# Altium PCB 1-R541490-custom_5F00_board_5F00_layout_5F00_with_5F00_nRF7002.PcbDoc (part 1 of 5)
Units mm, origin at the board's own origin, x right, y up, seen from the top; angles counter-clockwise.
Board outline 180 x 80 mm, 6 copper layers (Top Layer, GND 1, Signal 1, POWER, GND 2, Bottom Layer), stack 1.609 mm thick; 321 components, 275 nets, 828 pads, 1164 vias.
Unrouted connection lines stored in the file: 746.
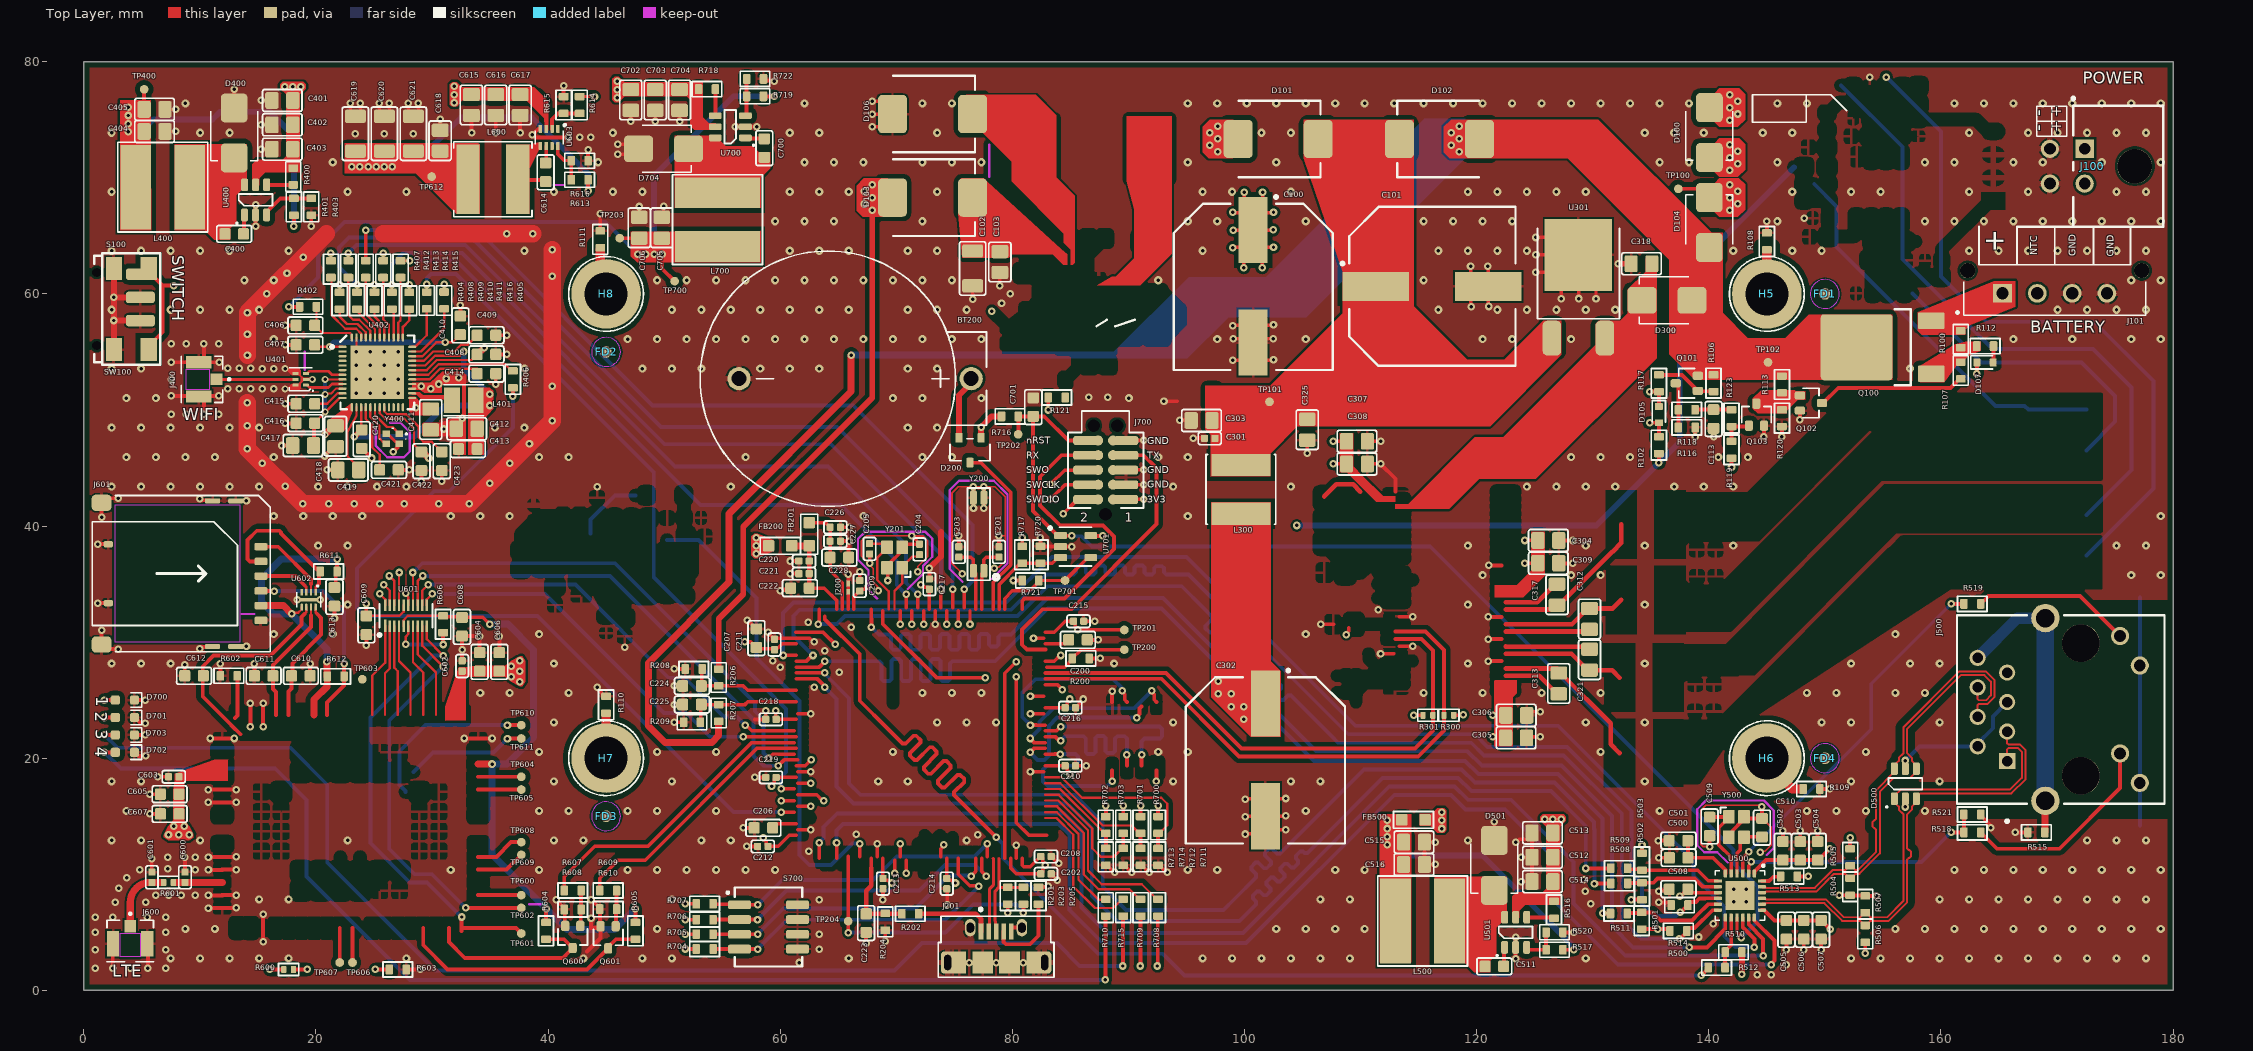
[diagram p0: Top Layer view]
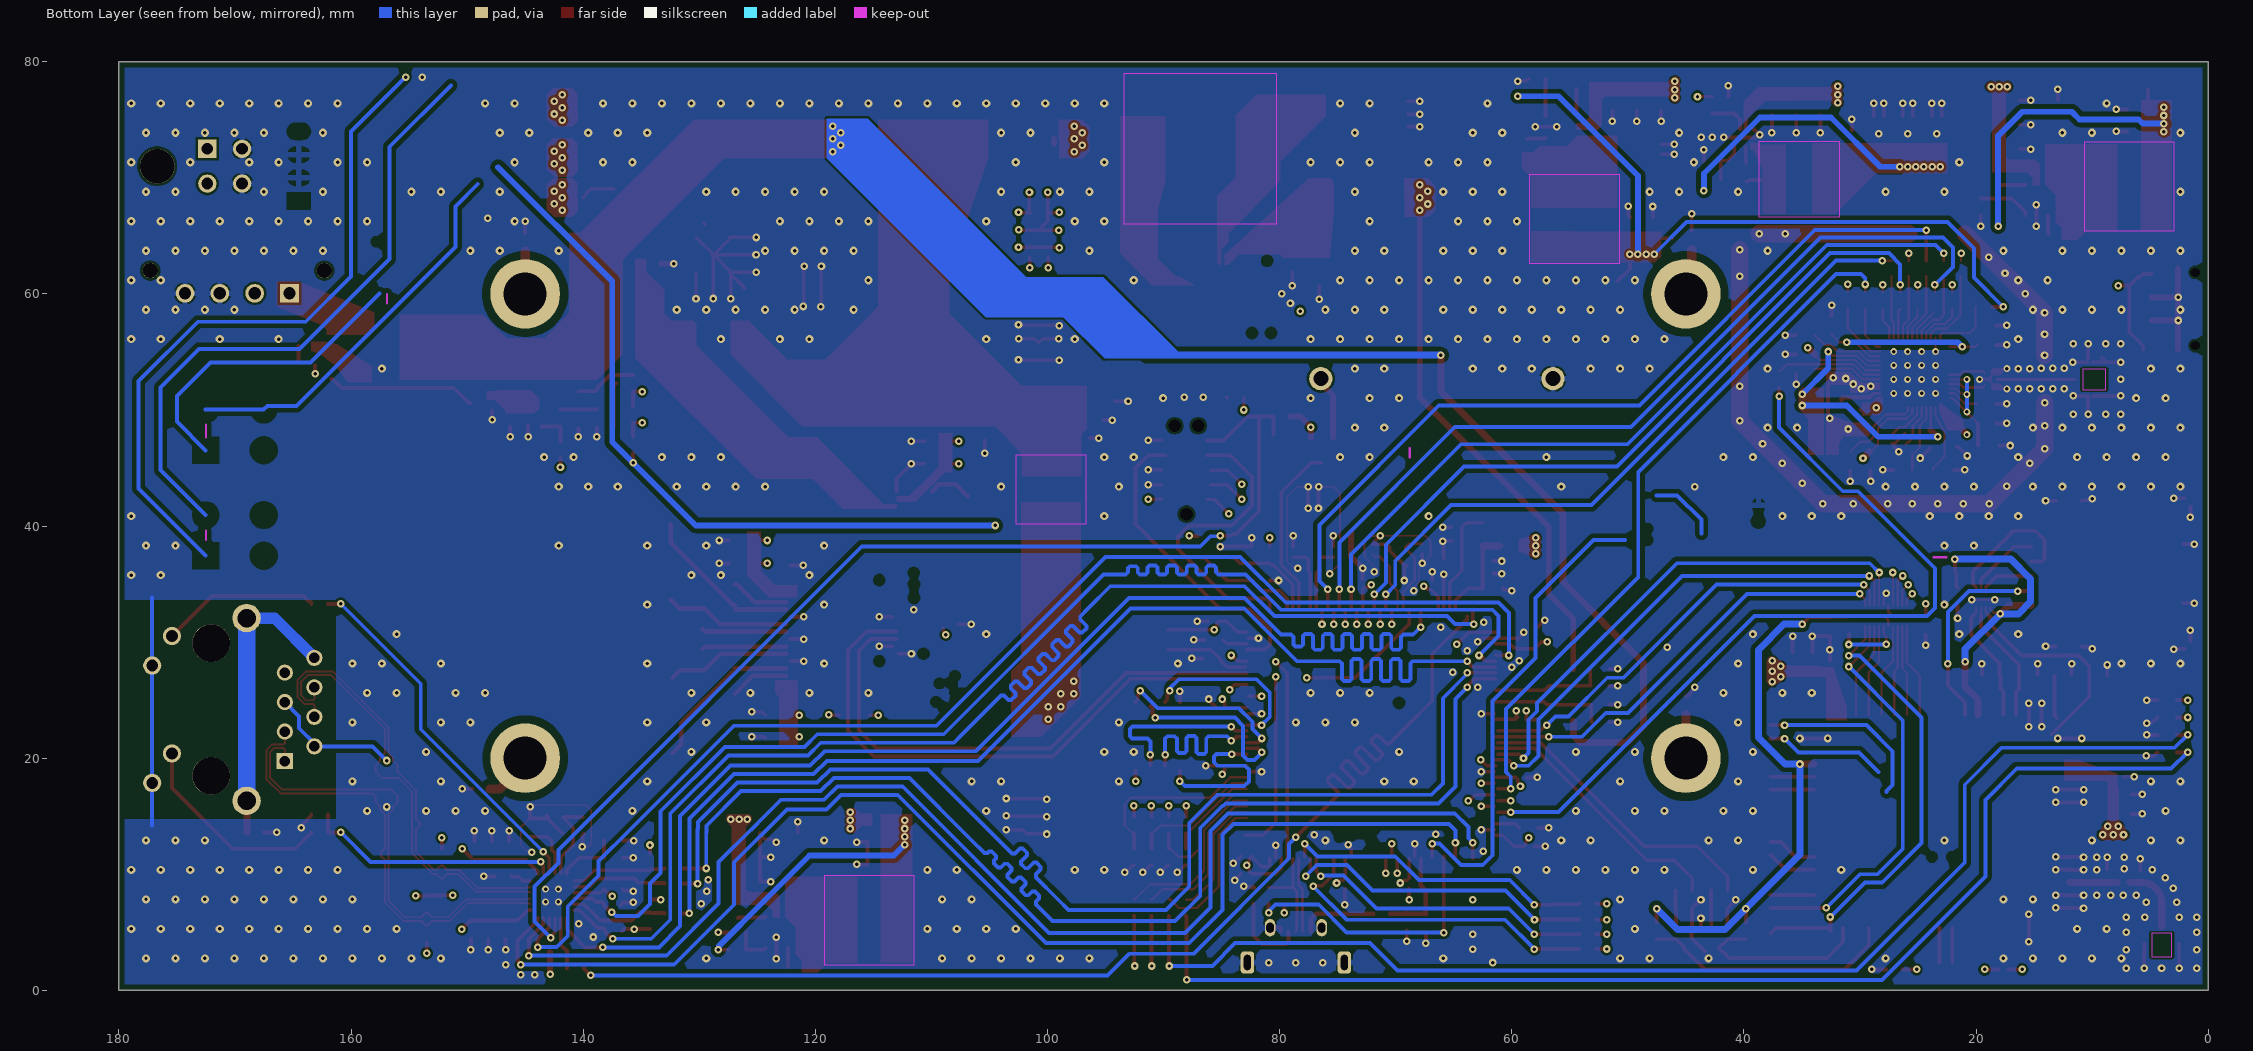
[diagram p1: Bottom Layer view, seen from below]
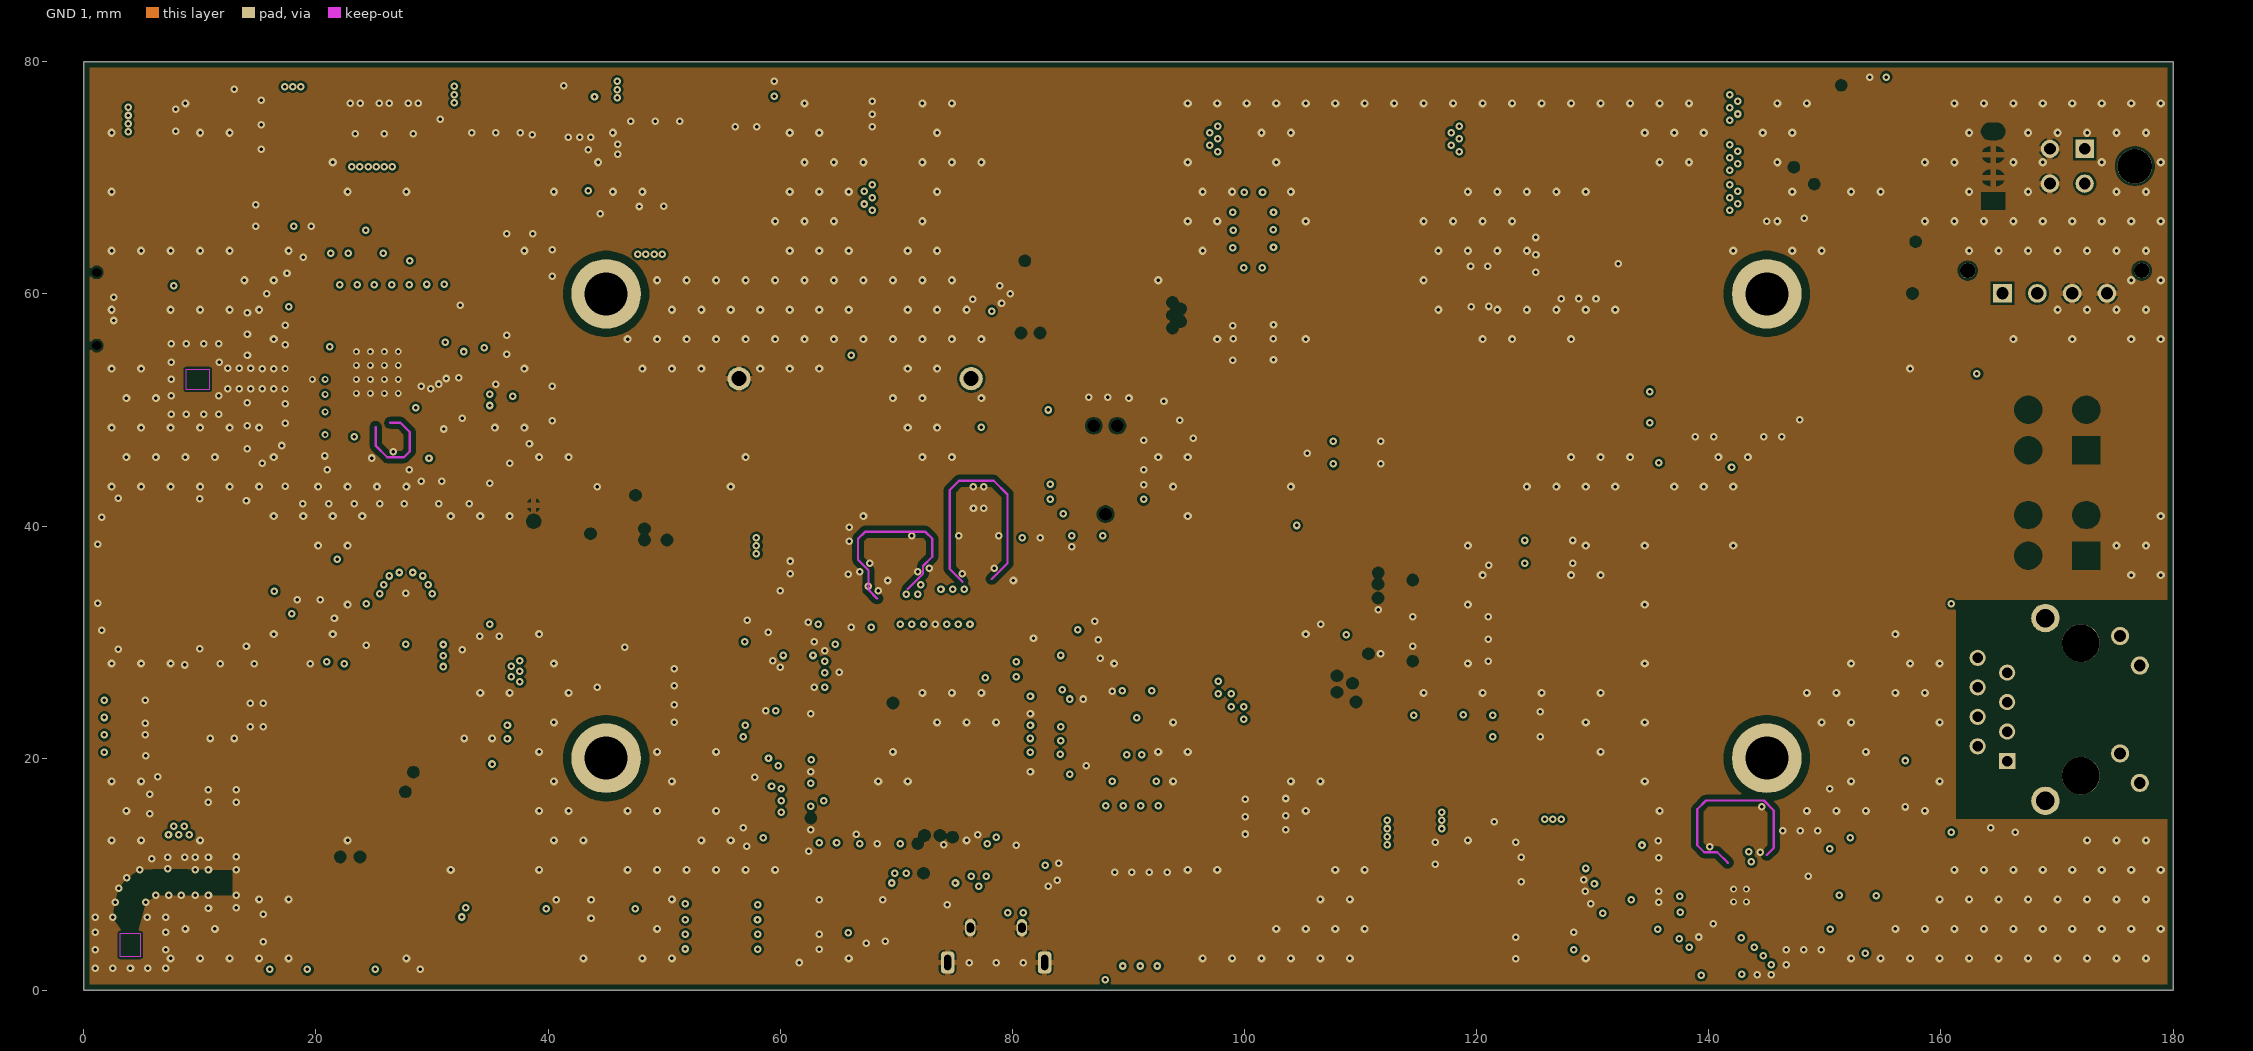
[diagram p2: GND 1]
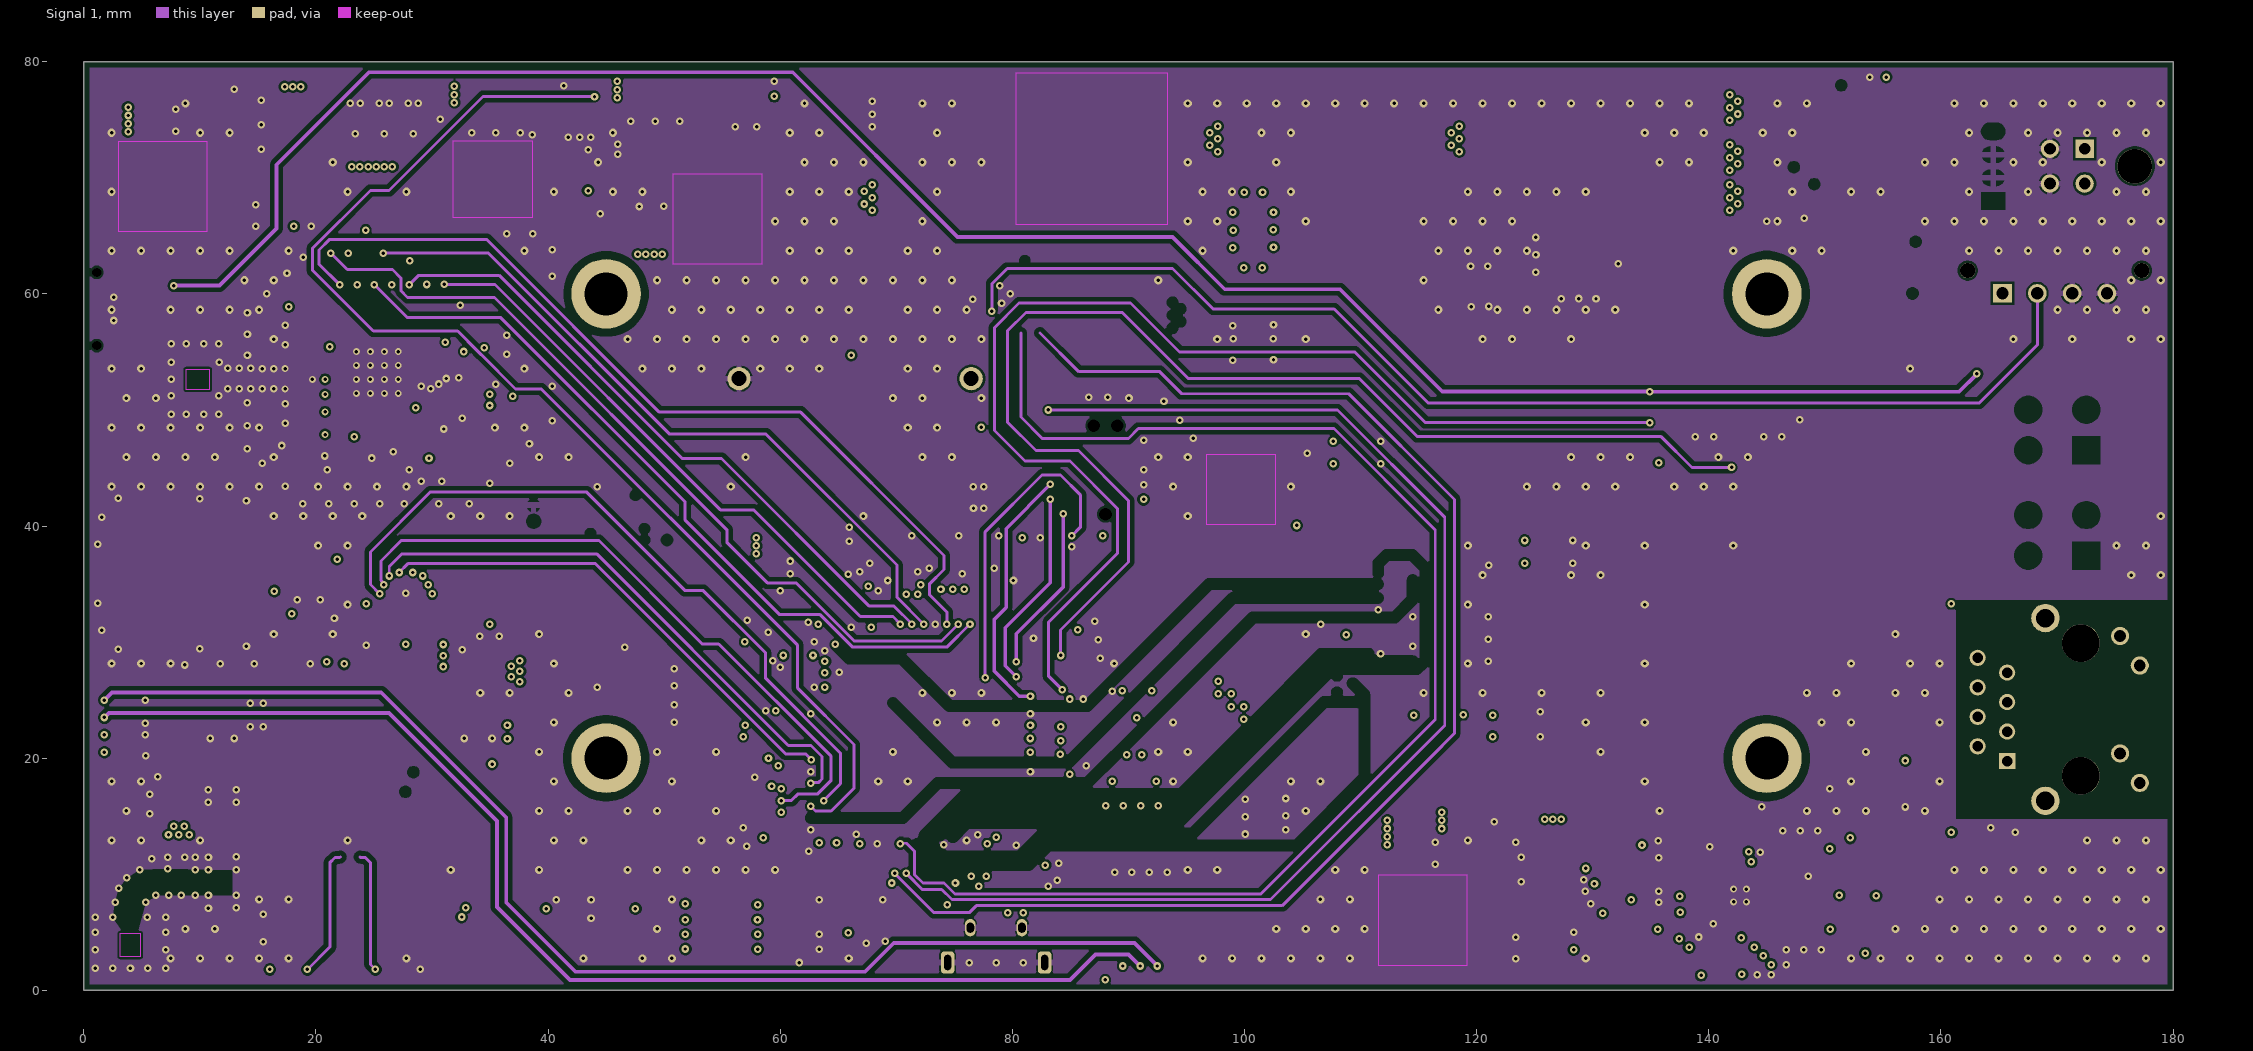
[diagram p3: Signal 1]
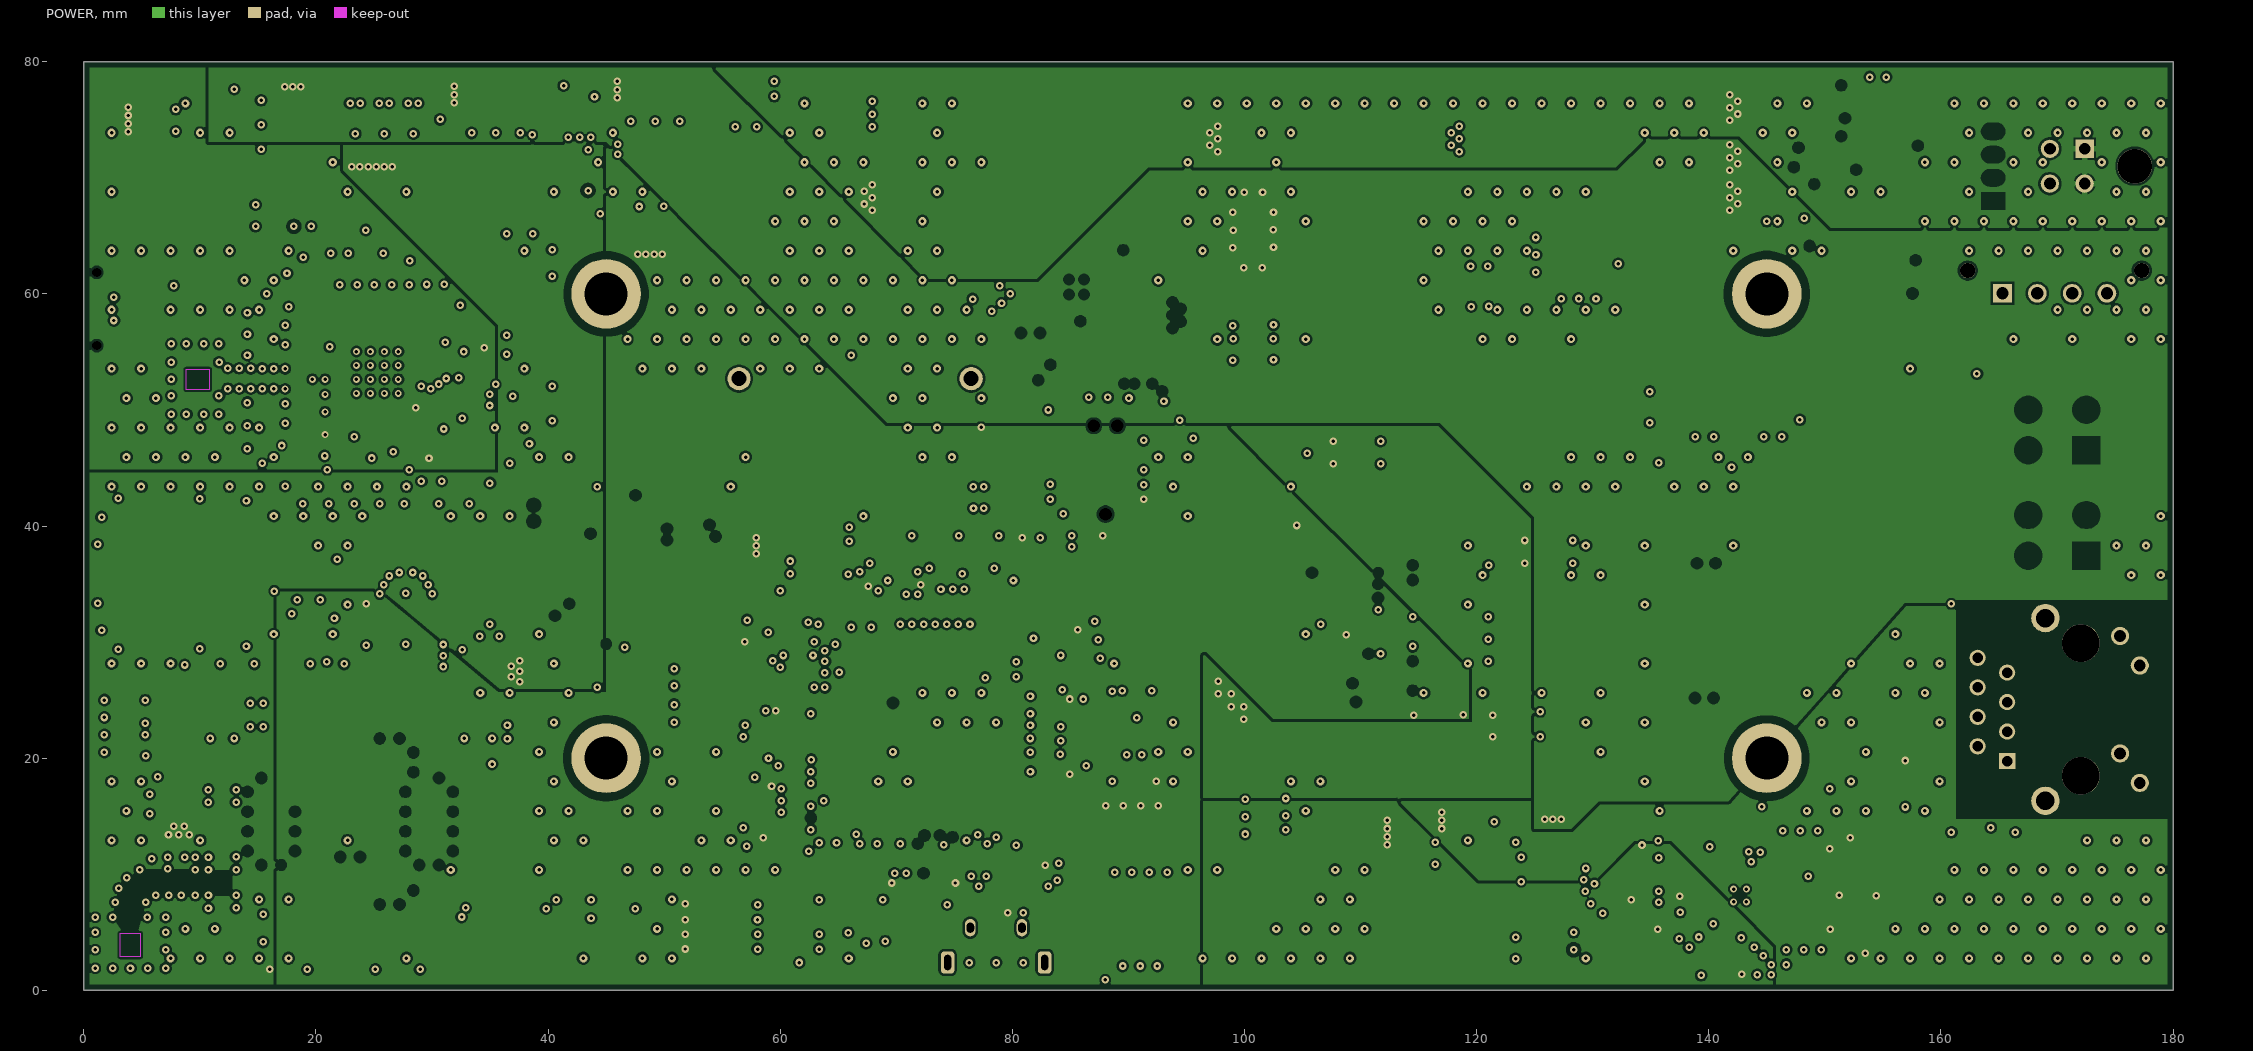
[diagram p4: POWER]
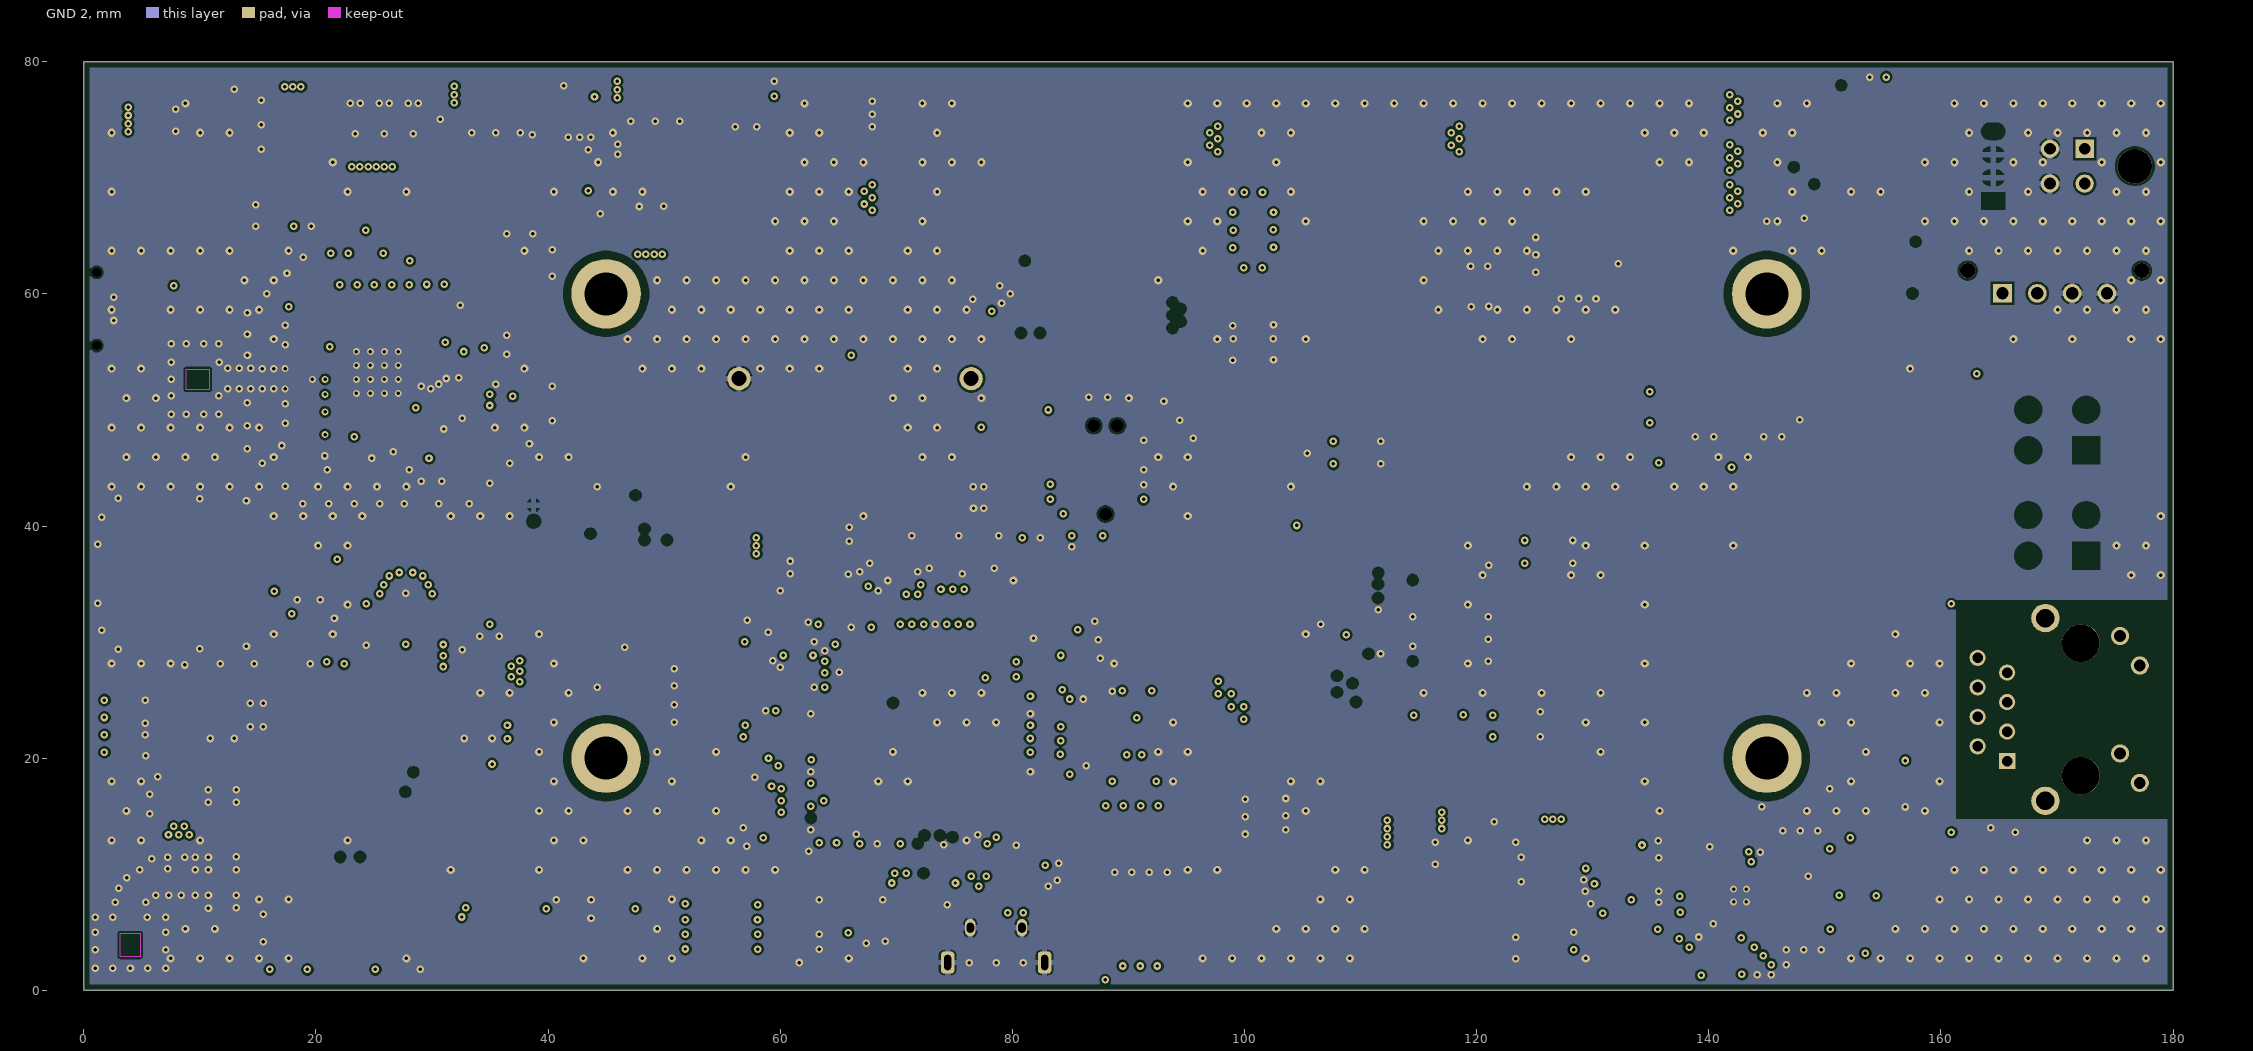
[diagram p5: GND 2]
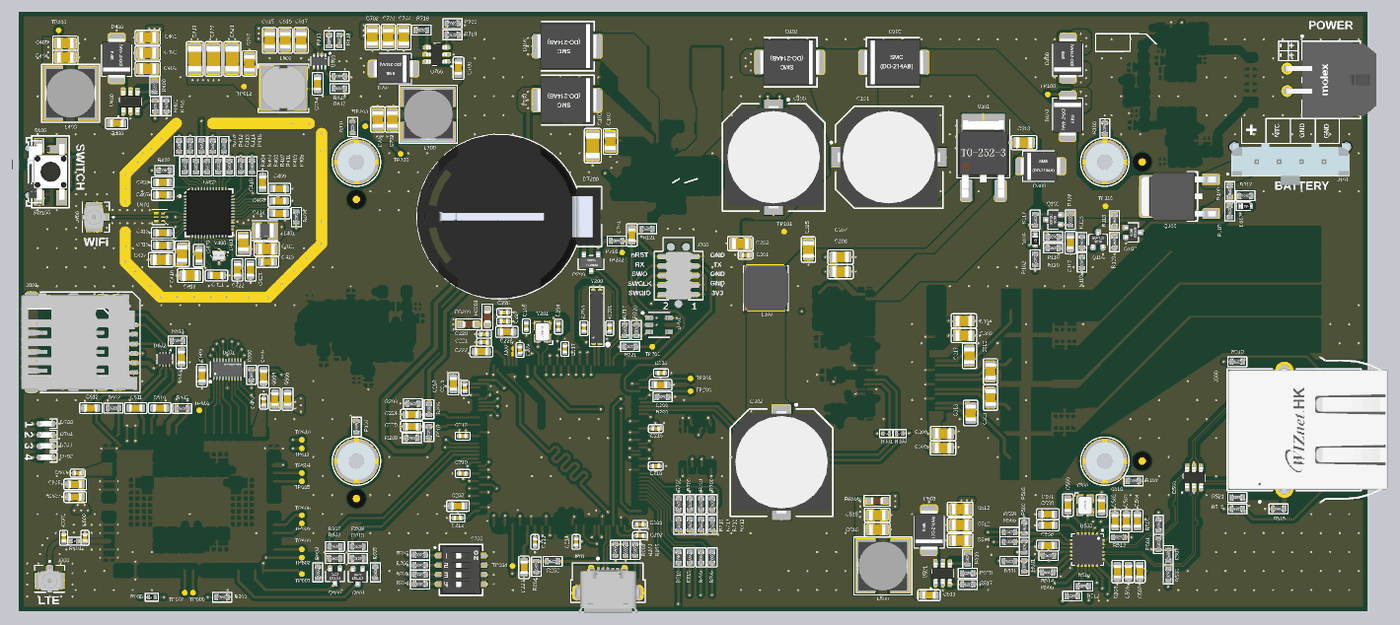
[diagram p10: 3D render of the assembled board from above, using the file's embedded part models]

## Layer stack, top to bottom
Top Solder: solder mask 0.0254, Dk 4
Top Layer: signal copper 0.035
Dielectric 1: prepreg 0.203, Dk 4.4
GND 1: signal copper 0.03
Dielectric 3: core 0.25, Dk 4.6
Signal 1: signal copper 0.03
Dielectric 4: prepreg 0.203, Dk 4.4
Dielectric 2: prepreg 0.107, Dk 4.1
Dielectric 5: prepreg 0.203, Dk 4.4
POWER: signal copper 0.03
Dielectric 6: core 0.25, Dk 4.6
GND 2: signal copper 0.03
Dielectric 8: prepreg 0.203, Dk 4.4
Bottom Layer: signal copper 0.035
Bottom Solder: solder mask 0.0254, Dk 4

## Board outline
0,0 0,80 180,80 180,0

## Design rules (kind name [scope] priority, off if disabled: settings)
BoardOutlineClearance [All] p1: gap=0.5 ignorepadtopadclearanceinfootprint=FALSE
Clearance Clearance_LTE [InNetClass('ANT_LTE')] p1: gap=0.155 ignorepadtopadclearanceinfootprint=TRUE
Clearance Clearance_BLE [InNetClass('ANT_BLE')] p2: gap=0.15 ignorepadtopadclearanceinfootprint=TRUE
Clearance Clearance_QSPI [InNetClass('QSPI')] p3: gap=0.2 ignorepadtopadclearanceinfootprint=TRUE except(0.4: Arc-Fill Arc-Poly Arc-Region Track-Fill Track-Poly Track-Region)
Clearance Clearance_RMII [InNetClass('RMII')] p4: gap=0.2 ignorepadtopadclearanceinfootprint=TRUE except(0.4: Arc-Fill Arc-Poly Arc-Region Track-Fill Track-Poly Track-Region)
Clearance "Clearance_Dif To Poly" [InNetClass('USB') or InNetClass('Ethernet')] p5: gap=0.15 ignorepadtopadclearanceinfootprint=TRUE except(0.6: Track-Poly)
Clearance Clearance_H5-H8 [InNet('NetH5_1') or InNet('NetH6_1') or InNet('NetH7_1') or InNet('NetH8_1')] p6: gap=0.7 ignorepadtopadclearanceinfootprint=TRUE
Clearance Clearance_All [All] p7: gap=0.2 ignorepadtopadclearanceinfootprint=TRUE except(0.15: Arc-Arc Arc-Track Arc-SMDPad Arc-Via Arc-Fill Arc-Poly Arc-Region Track-Track Track-SMDPad Track-Via Track-Fill Track-Region SMDPad-Via SMDPad-Fill SMDPad-Region; 0.3: Poly-Poly; 0.4: Track-Poly SMDPad-Poly)
ComponentClearance [All] p1: gap=0 collisioncheckmode=3 verticalgap=0 showdistances=FALSE
DiffPairsRouting Diff_100 [InDifferentialPair('RD') or InDifferentialPair('TD')] p1: maxlimit=0.15 minlimit=0.127 mostfreqgap=0.127 toplayer_mingap=0.15 toplayer_prefgap=0.15 toplayer_minwidth=0.17 toplayer_maxwidth=0.17 toplayer_prefwidth=0.17 bottomlayer_mingap=0.15 bottomlayer_prefgap=0.15 bottomlayer_minwidth=0.17 bottomlayer_maxwidth=0.17 bottomlayer_prefwidth=0.17 impedanceprofiledriven=TRUE impedanceprofileid={3A594C90-DEC5-4F1F-8E79-E24C382BD90D} impedanceprofilevalue=100.000000 maxuncoupledlength=12.7
DiffPairsRouting Diff_90 [InDifferentialPair('USB')] p2: maxlimit=0.25 minlimit=0.127 mostfreqgap=0.127 toplayer_mingap=0.2 toplayer_maxgap=0.2 toplayer_prefgap=0.2 toplayer_minwidth=0.27 toplayer_maxwidth=0.27 toplayer_prefwidth=0.27 bottomlayer_mingap=0.2 bottomlayer_maxgap=0.2 bottomlayer_prefgap=0.2 bottomlayer_minwidth=0.27 bottomlayer_maxwidth=0.27 bottomlayer_prefwidth=0.27 impedanceprofiledriven=TRUE impedanceprofileid={268F52A2-5A94-457B-AB45-65FDFB8BE8B0} impedanceprofilevalue=90.000000 maxuncoupledlength=12.7
HoleSize [All] p1: absolutevalues=TRUE maxlimit=5 minlimit=0.3 maxpercent=80.000 minpercent=20.000
MatchedLengths xSignals_Ethernet_Group [InxSignalClass('Ethernet')] p1: tolerance=1.3 checknetsindiffpair=FALSE checkdiffpairvsdiffpair=TRUE checkxsignals=TRUE checkothers=TRUE usedelayunits=TRUE delaytolerance=330.000000
MatchedLengths xSignals_Ethernet_DP [InxSignalClass('Ethernet')] p2: tolerance=1.3 checknetsindiffpair=TRUE checkdiffpairvsdiffpair=FALSE checkxsignals=FALSE checkothers=FALSE usedelayunits=TRUE delaytolerance=1.600000
MatchedLengths xSignals_QSPI [InxSignalClass('QSPI')] p3: tolerance=1.3 checknetsindiffpair=FALSE checkdiffpairvsdiffpair=TRUE checkxsignals=TRUE checkothers=TRUE usedelayunits=TRUE delaytolerance=1.600000
MatchedLengths xSignals_RMII [InxSignalClass('RMII')] p4: tolerance=1.3 checknetsindiffpair=FALSE checkdiffpairvsdiffpair=TRUE checkxsignals=TRUE checkothers=TRUE usedelayunits=TRUE delaytolerance=1.600000
MinimumSolderMaskSliver [All] p1: minsoldermaskwidth=0.05
PasteMaskExpansion [All] p1: expansion=-0.05
PlaneClearance [All] p1: clearance=0.152
PlaneConnect [All] p1: planeconnectstyle=Direct reliefexpansion=0.508 reliefentries=4 reliefconductorwidth=0.254 reliefairgap=0.254
PolygonConnect PolygonConnect_All [All] p1: thpad.connectstyle=Relief thpad.reliefconductorwidth=0.5 thpad.reliefentries=4 thpad.polygonreliefangle="90 Angle" thpad.airgapwidth=0.15 smdpad.connectstyle=Relief smdpad.reliefconductorwidth=0.254 smdpad.reliefentries=4 smdpad.polygonreliefangle="90 Angle" smdpad.airgapwidth=0.15 via.connectstyle=Direct via.reliefconductorwidth=0.254 via.reliefentries=4 via.polygonreliefangle="90 Angle" via.airgapwidth=0.254
RoutingVias [All] p1: holewidth=0.3 width=0.6 viastyle="Through Hole" minholewidth=0.3 minwidth=0.3 maxholewidth=0.6 maxwidth=1
SilkToSilkClearance [All] p1: silktosilkclearance=0.2
SilkToSolderMaskClearance [IsPad] p1: minsilkscreentomaskgap=0.025 clearancetoexposedcopper=TRUE
SolderMaskExpansion [All] p1: expansion=0.05 istentingtop=FALSE
SupplyNets "Schematic Supply Nets_9" [InNet('VDD_MCU')] p1: voltage=0.000
SupplyNets "Schematic Supply Nets_7" [InNet('VBAT_nRF')] p2: voltage=0.000
SupplyNets "Schematic Supply Nets_18" [InNet('+VCC_Ampl')] p3: voltage=0.000
SupplyNets "Schematic Supply Nets_17" [InNet('VDDA')] p4: voltage=0.000
SupplyNets "Schematic Supply Nets_15" [InNet('VREF+')] p5: voltage=0.000
SupplyNets "Schematic Supply Nets_13" [InNet('PVDD')] p6: voltage=0.000
SupplyNets "Schematic Supply Nets_12" [InNet('VIN')] p7: voltage=0.000
SupplyNets "Schematic Supply Nets_11" [InNet('GND')] p8: voltage=0.000
SupplyNets "Schematic Supply Nets_4" [InNet('+1.8V_modem')] p9: voltage=0.000
SupplyNets "Schematic Supply Nets" [InNet('+VCC_modem')] p10: voltage=0.000
SupplyNets "Schematic Supply Nets_8" [InNet('VCC_Ethr')] p11: voltage=0.000
SupplyNets "Schematic Supply Nets_6" [InNet('VCC')] p12: voltage=0.000
SupplyNets "Schematic Supply Nets_3" [InNet('VBAT')] p13: voltage=0.000
SupplyNets "Schematic Supply Nets_2" [InNet('PWRIOVDD')] p14: voltage=0.000
SupplyNets "Schematic Supply Nets_1" [InNet('VDD_BUCK')] p15: voltage=0.000
Width RF_ANT_BLE [InNetClass('ANT_BLE')] p1: maxlimit=0.25 minlimit=0.152 preferedwidth=0.234 toplayer_minwidth=0.25 toplayer_prefwidth=0.25 impedanceprofiledriven=TRUE impedanceprofileid={3CCB0671-2807-4B09-B0E4-ECFB67FC63CC} impedanceprofilevalue=50.000000 minimp=50.000000 maximp=50.000000 favimp=50.000000
Width RMII [InNetClass('RMII')] p2: maxlimit=0.478 minlimit=0.152 preferedwidth=0.256 toplayer_minwidth=0.3 toplayer_maxwidth=0.335 toplayer_prefwidth=0.335 midlayer1_minwidth=0.256 midlayer1_maxwidth=0.256 midlayer2_minwidth=0.256 midlayer2_maxwidth=0.256 bottomlayer_minwidth=0.3 bottomlayer_maxwidth=0.335 bottomlayer_prefwidth=0.335 impedanceprofiledriven=TRUE impedanceprofileid={89E4D563-145F-4F12-8B66-BC4C088131D8} impedanceprofilevalue=50.000000 minimp=50.000000 maximp=50.000000 favimp=50.000000
Width RF_ANT_LTE_1 [InNetClass('ANT_LTE')] p3: maxlimit=0.62 minlimit=0.152 preferedwidth=0.234 toplayer_minwidth=0.62 toplayer_prefwidth=0.62 impedanceprofiledriven=TRUE impedanceprofileid={F6C68C6A-9B4C-40B1-A6B1-C1A082B88F94} impedanceprofilevalue=50.000000 minimp=50.000000 maximp=50.000000 favimp=50.000000
Width "Tracks Z=50 Ohm" [InNetClass('50 Ohm')] p4: maxlimit=0.344 minlimit=0.256 preferedwidth=0.344 toplayer_minwidth=0.335 toplayer_maxwidth=0.335 toplayer_prefwidth=0.335 midlayer1_maxwidth=0.256 midlayer1_prefwidth=0.256 midlayer2_maxwidth=0.256 midlayer2_prefwidth=0.256 bottomlayer_minwidth=0.335 bottomlayer_maxwidth=0.335 bottomlayer_prefwidth=0.335 impedanceprofiledriven=TRUE impedanceprofileid={89E4D563-145F-4F12-8B66-BC4C088131D8} impedanceprofilevalue=50.000000 minimp=50.000000 maximp=50.000000 favimp=50.000000
Width ALL_TRACKS [All] p5: maxlimit=5 minlimit=0.14 preferedwidth=0.152 midlayer3_prefwidth=0.254 midlayer4_prefwidth=0.254 minimp=50.000000 maximp=50.000000 favimp=50.000000
21 further rules are at their usual default settings.

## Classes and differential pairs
net class QSPI: CLK CS HOLD MISO MOSI WP
net class SIM: SIM_C_CLK SIM_C_DATA SIM_C_RST SIM_CLK sim_connector.SIM_DATA sim_connector.SIM_RST
differential pair class DIFF90: USB
differential pair class DIFF100: RD TD
net class USB: USB_N USB_P
net class RMII: NetR501_1 NetR502_1 NetR503_1 RMII_CRS_DV RMII_MDC RMII_MDIO RMII_REF_CLK RMII_RX_ER RMII_RXD0 RMII_RXD1 RMII_TX_EN RMII_TXD0 RMII_TXD1
net class Ethernet: RD_N RD_P TD_N TD_P
net class ANT_LTE: ANT_LTE_1 ANT_LTE_2
net class ANT_BLE: NetJ400_1 TXRF0 TXRF1
net class "50 Ohm": NetR501_1 NetR502_1 NetR503_1 RMII_CRS_DV RMII_MDC RMII_MDIO RMII_REF_CLK RMII_RX_ER RMII_RXD0 RMII_RXD1 RMII_TX_EN RMII_TXD0 RMII_TXD1
component class Power: C100 C101 C102 C113 D100 D101 D102 D103 D104 D105 D106 D107 J100 J101 Q100 Q101 Q102 Q103 R100 R102 R106 R107 R112 R113 R116 R117 R118 R119 R120 R121 R123 S100 SW100 TP100 TP101 TP102
component class MCU: BT200 C200 C201 C202 C203 C204 C205 C206 C207 C208 C209 C210 C211 C212 C213 C214 C215 C216 C217 C218 C219 C220 C221 C222 C223 C224 C225 C226 C227 C228 D200 FB200 FB201 J200 J201 R200 R201 R202 R203 R204 R205 R206 R207 R208 R209 TP200 TP201 TP202 TP203 TP204 Y200 Y201
component class Debug: C700 C701 C702 C703 C704 C705 C706 D700 D701 D702 D703 D704 J700 L700 R700 R701 R702 R703 R704 R705 R706 R707 R708 R709 R710 R711 R712 R713 R714 R715 R716 R717 R718 R719 R720 R721 R722 S700 TP700 TP701 U700 U701
component class "LTE Modem": C600 C601 C602 C603 C604 C605 C606 C607 C608 C609 C610 C611 C612 C613 C614 C615 C616 C617 C618 C619 C620 C621 J600 J601 L600 Q600 Q601 R600 R601 R602 R603 R604 R605 R606 R607 R608 R609 R610 R611 R612 R613 R614 R615 R616 TP600 TP601 TP602 TP603 TP604 TP605 TP606 TP607 TP608 TP609 TP610 TP611 TP612 U601 U602 U603
component class Ethernet: C500 C501 C502 C503 C504 C505 C506 C507 C508 C509 C510 C511 C512 C513 C514 C515 C516 D500 D501 FB500 J500 L500 R500 R501 R502 R503 R504 R505 R506 R507 R508 R509 R510 R511 R512 R513 R514 R515 R516 R517 R518 R519 R520 R521 U500 U501 Y500
component class Amplifier: C301 C302 C303 C304 C305 C306 C307 C308 C309 C312 C313 C317 C318 C321 C325 D300 L300 R300 R301 U301
component class WiFi: C400 C401 C402 C403 C404 C405 C406 C407 C408 C409 C410 C411 C412 C413 C414 C415 C416 C417 C418 C419 C420 C421 C422 C423 D400 J400 L400 L401 R400 R401 R402 R403 R404 R405 R406 R407 R408 R409 R410 R411 R412 R413 R414 R415 R416 TP400 U400 U401 U402 Y400
component class MSheet: FD1 FD2 FD3 FD4 GS1 H5 H6 H7 H8 R108 R109 R110 R111
differential pair USB: +USB_P -USB_N
differential pair TD: +TD_P -TD_N
differential pair RD: +RD_P -RD_N

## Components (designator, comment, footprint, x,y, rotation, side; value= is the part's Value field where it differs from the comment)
BT200 "BH-25F-1" BH-25F-1 64.45,52.7 r0 top
C100 "EMVA500ARA471MKG5S" EMVA500ARA471MKG5S 100.75,60.65 r270 top value=470µF
C101 "EMVA500ARA471MKG5S" EMVA500ARA471MKG5S 116.15,60.65 r0 top value=470µF
C102 "GRM31CR71H475KA12L" B_Cap_1206_KEM 76.575,62.196 r90 top value=4.7µF
C103 "CC0805KRX7R9BB104" B_Cap_0805_KEM 78.925,62.746 r90 top value=100nF
C113 "GRM188R61C106KAALJ" B_Cap_0603_KEM 140.407,49.226 r90 top value=10µF
C200 "CL10B225KP8NNNC" B_Cap_0603_KEM 85.65,30.2 r180 top value=2.2µF
C201 "GRM1555C1H3R3WA01D" B_Cap_0402_KEM 78.842,37.775 r270 top value=3.3pF
C202 "EMK105BJ105KV-F" B_Cap_0402_KEM 82.899,10.04 r0 top value=1µF
C203 "GRM1555C1H3R3WA01D" B_Cap_0402_KEM 75.387,37.775 r90 top value=3.3pF
C204 "CC0402BRNPO9BN2R7" B_Cap_0402_KEM 72,37.99 r90 top value=2.7pF
C205 "CC0402BRNPO9BN2R7" B_Cap_0402_KEM 67.7,38.04 r270 top value=2.7pF
C206 "CL10B225KP8NNNC" B_Cap_0603_KEM 58.55,14 r0 top value=2.2µF
C207 "GCM188R71H104KA57D" B_Cap_0603_KEM 57.95,30.35 r270 top value=100nF
C208 "CL05A475MO5NUNC" B_Cap_0402_KEM 82.899,11.54 r180 top value=4.7µF
C209 "GRM155R71H104ME14D" B_Cap_0402_KEM 66.85,34.861 r270 top value=100nF
C210 "GRM155R71H104ME14D" B_Cap_0402_KEM 85,19.35 r180 top value=100nF
C211 "GRM155R71H104ME14D" B_Cap_0402_KEM 59.5,29.8 r270 top value=100nF
C212 "GRM155R71H104ME14D" B_Cap_0402_KEM 58.5,12.4 r0 top value=100nF
C213 "GRM155R71H104ME14D" B_Cap_0402_KEM 68.85,9.2 r90 top value=100nF
C214 "GRM155R71H104ME14D" B_Cap_0402_KEM 74.35,9.2 r90 top value=100nF
C215 "GRM155R71H104ME14D" B_Cap_0402_KEM 85.7,31.8 r180 top value=100nF
C216 "GRM155R71H104ME14D" B_Cap_0402_KEM 85,24.35 r180 top value=100nF
C217 "GRM155R71H104ME14D" B_Cap_0402_KEM 72.85,35 r270 top value=100nF
C218 "GRM155R71H104ME14D" B_Cap_0402_KEM 59.2,23.35 r0 top value=100nF
C219 "GRM155R71H104ME14D" B_Cap_0402_KEM 59.2,18.35 r0 top value=100nF
C220 "EMK105BJ105KV-F" B_Cap_0402_KEM 62.05,36.989 r0 top value=1µF
C221 "GRM155R71H104ME14D" B_Cap_0402_KEM 62.05,35.899 r0 top value=100nF
C222 "CC0603MRX7R9BB103" B_Cap_0603_KEM 61.7,34.654 r0 top value=10nF
C223 "GCM188R71H104KA57D" B_Cap_0603_KEM 67.4,5.8 r90 top value=100nF
C224 "GCM188R71H104KA57D" B_Cap_0603_KEM 52.4,26.225 r0 top value=100nF
C225 "GCM188R71H104KA57D" B_Cap_0603_KEM 52.4,24.625 r0 top value=100nF
C226 "EMK105BJ105KV-F" B_Cap_0402_KEM 64.75,39.9 r180 top value=1µF
C227 "GRM155R71H104ME14D" B_Cap_0402_KEM 64.75,38.7 r180 top value=100nF
C228 "CC0603MRX7R9BB103" B_Cap_0603_KEM 65.1,37.29 r180 top value=10nF
C301 "CC0402JRX7R9BB222" B_Cap_0402_KEM 97,47.55 r0 top value=2.2nF
C302 "EMVA500ARA471MKG5S" EMVA500ARA471MKG5S 101.8,19.85 r270 top value=470µF
C303 "CC0805KRX7R9BB104" B_Cap_0805_KEM 96.3,49.1 r0 top value=100nF
C304 "CL21B105KBFNNNG" B_Cap_0805_KEM 126.175,38.757 r180 top value=1µF
C305 "CL21B105KBFNNNG" B_Cap_0805_KEM 123.391,21.757 r180 top value=1µF
C306 "CC0805KRX7R9BB104" B_Cap_0805_KEM 123.407,23.69 r180 top value=100nF
C307 "CL21B105KBFNNNG" B_Cap_0805_KEM 109.69,47.3 r180 top value=1µF
C308 "CC0805KRX7R9BB104" B_Cap_0805_KEM 109.69,45.35 r180 top value=100nF
C309 "CC0805KRX7R9BB104" B_Cap_0805_KEM 126.175,36.803 r180 top value=100nF
C312 "CL21B105KBFNNNG" B_Cap_0805_KEM 129.725,28.49 r90 top value=1µF
C313 "CL21B105KBFNNNG" B_Cap_0805_KEM 127.075,26.44 r270 top value=1µF
C317 "CL21B105KBFNNNG" B_Cap_0805_KEM 126.925,34.09 r90 top value=1µF
C318 "CC0805KRX7R9BB104" B_Cap_0805_KEM 134.2,62.6 r0 top value=100nF
C321 "CL21B105KBFNNNG" B_Cap_0805_KEM 129.725,32.002 r270 top value=1µF
C325 "CC0805KRX7R9BB104" B_Cap_0805_KEM 105.4,48.3 r90 top value=100nF
C400 "GCM188R71H104KA57D" B_Cap_0603_KEM 12.96,65.17 r0 top value=100nF
C401 "CL21B105KBFNNNG" B_Cap_0805_KEM 17.108,76.67 r180 top value=1µF
C402 "CL21B105KBFNNNG" B_Cap_0805_KEM 17.108,74.57 r180 top value=1µF
C403 "CC0805KRX7R9BB104" B_Cap_0805_KEM 17.108,72.47 r0 top value=100nF
C404 "GRM21BR71C475KE51L" B_Cap_0805_KEM 6.1,75.9 r180 top value=4.7µF
C405 "GRM21BR71C475KE51L" B_Cap_0805_KEM 6.1,74 r180 top value=4.7µF
C406 "CL10B225KP8NNNC" B_Cap_0603_KEM 19.094,57.287 r0 top value=2.2µF
C407 "GCM188R71H104KA57D" B_Cap_0603_KEM 19.094,55.612 r0 top value=100nF
C408 "CL10B225KP8NNNC" B_Cap_0603_KEM 34.694,54.787 r180 top value=2.2µF
C409 "CL10B105KA8NNNC" B_Cap_0603_KEM 34.694,56.437 r180 top value=1µF
C410 "CL10B225KP8NNNC" B_Cap_0603_KEM 32.444,57.287 r270 top value=2.2µF
C411 "GRM21BR71C475KE51L" B_Cap_0805_KEM 29.894,49.187 r90 top value=4.7µF
C412 "GRM21BR71C475KE51L" B_Cap_0805_KEM 32.994,48.387 r0 top value=4.7µF
C413 "CL10A474KB8NNNC" B_Cap_0603_KEM 33.094,46.637 r0 top value=470nF
C414 "CC0603MRX7R9BB103" B_Cap_0603_KEM 34.694,53.137 r180 top value=10nF
C415 "CL10A474KB8NNNC" B_Cap_0603_KEM 19.094,50.537 r0 top value=470nF
C416 "GCM188R71H104KA57D" B_Cap_0603_KEM 19.094,48.866 r0 top value=100nF
C417 "GRM21BR71C475KE51L" B_Cap_0805_KEM 18.894,46.937 r0 top value=4.7µF
C418 "GRM21BR71C475KE51L" B_Cap_0805_KEM 21.694,47.737 r90 top value=4.7µF
C419 "CC0805KRX7R9BB223" B_Cap_0805_KEM 22.794,44.837 r0 top value=22nF
C420 "C0603C224K4RAC7411" B_Cap_0603_KEM 23.944,47.487 r270 top value=220nF
C421 "CL10B225KP8NNNC" B_Cap_0603_KEM 26.294,44.837 r180 top value=2.2µF
C422 "CL10B105KA8NNNC" B_Cap_0603_KEM 29.094,45.587 r90 top value=1µF
C423 "CL10B105KA8NNNC" B_Cap_0603_KEM 30.844,45.587 r90 top value=1µF
C500 "VJ0603Y471KLAAJ32" B_Cap_0603_KEM 137.403,11.422 r0 top value=470pF
C501 "CL10B105KA8NNNC" B_Cap_0603_KEM 137.388,12.898 r0 top value=1µF
C502 "GCM188R71H104KA57D" B_Cap_0603_KEM 146.378,12.022 r270 top value=100nF
C503 "GCM188R71H104KA57D" B_Cap_0603_KEM 147.878,12.022 r270 top value=100nF
C504 "GCM188R71H104KA57D" B_Cap_0603_KEM 149.378,12.022 r270 top value=100nF
C505 "GCM188R71H104KA57D" B_Cap_0603_KEM 146.678,5.222 r90 top value=100nF
C506 "GCM188R71H104KA57D" B_Cap_0603_KEM 148.178,5.222 r90 top value=100nF
C507 "GCM188R71H104KA57D" B_Cap_0603_KEM 149.678,5.222 r90 top value=100nF
C508 "GCM188R71H104KA57D" B_Cap_0603_KEM 137.388,8.723 r0 top value=100nF
C509 "06035A220JAT2A" B_Cap_0603_KEM 140.066,14.121 r90 top value=22pF
C510 "06035A220JAT2A" B_Cap_0603_KEM 144.578,14.022 r270 top value=22pF
C511 "GCM188R71H104KA57D" B_Cap_0603_KEM 121.519,2.069 r0 top value=100nF
C512 "CL21B105KBFNNNG" B_Cap_0805_KEM 125.667,11.469 r180 top value=1µF
C513 "CL21B105KBFNNNG" B_Cap_0805_KEM 125.667,13.569 r180 top value=1µF
C514 "CC0805KRX7R9BB104" B_Cap_0805_KEM 125.667,9.369 r0 top value=100nF
C515 "GRM21BR71C475KE51L" B_Cap_0805_KEM 114.6,12.772 r180 top value=4.7µF
C516 "GRM21BR71C475KE51L" B_Cap_0805_KEM 114.6,10.847 r180 top value=4.7µF
C600 "Cap TBD, , 0402," B_Cap_0402_KEM 8.72,9.75 r270 top
C601 "Cap TBD, , 0402," B_Cap_0402_KEM 5.87,9.74 r270 top
C602 "C0402C390J5GACTU" B_Cap_0402_KEM 32.6,27.944 r90 top value=39pF
C603 "C0402C390J5GACTU" B_Cap_0402_KEM 7.75,18.4 r0 top value=39pF
C604 "GCM188R71H104KA57D" B_Cap_0603_KEM 34.1,28.3 r90 top value=100nF
C605 "GCM188R71H104KA57D" B_Cap_0603_KEM 7.4,16.9 r0 top value=100nF
C606 "CL10A226MO7JZNC" B_Cap_0603_KEM 35.8,28.3 r90 top value=22µF
C607 "CL10A226MO7JZNC" B_Cap_0603_KEM 7.4,15.2 r0 top value=22µF
C608 "GCM188R71H104KA57D" B_Cap_0603_KEM 32.586,31.32 r270 top value=100nF
C609 "GCM188R71H104KA57D" B_Cap_0603_KEM 24.35,31.45 r270 top value=100nF
C610 "06035A220JAT2A" B_Cap_0603_KEM 18.7,27.1 r180 top value=22pF
C611 "06035A220JAT2A" B_Cap_0603_KEM 15.5,27.1 r0 top value=22pF
C612 "06035A220JAT2A" B_Cap_0603_KEM 9.5,27.1 r0 top value=22pF
C613 "CL10B105KA8NNNC" B_Cap_0603_KEM 21.6,33.9 r90 top value=1µF
C614 "GCM188R71H104KA57D" B_Cap_0603_KEM 39.794,70.476 r90 top value=100nF
C615 "CL21B105KBFNNNG" B_Cap_0805_KEM 33.394,76.276 r270 top value=1µF
C616 "CL21B105KBFNNNG" B_Cap_0805_KEM 35.494,76.276 r270 top value=1µF
C617 "CC0805KRX7R9BB104" B_Cap_0805_KEM 37.594,76.276 r90 top value=100nF
C618 "CC0805KRX7R9BB104" B_Cap_0805_KEM 30.7,73.2 r270 top value=100nF
C619 "EMK316BB7226ML-T" B_Cap_1206_KEM 23.4,73.8 r270 top value=22µF
C620 "EMK316BB7226ML-T" B_Cap_1206_KEM 25.9,73.8 r270 top value=22µF
C621 "EMK316BB7226ML-T" B_Cap_1206_KEM 28.4,73.8 r270 top value=22µF
C700 "GCM188R71H104KA57D" B_Cap_0603_KEM 58.63,72.56 r90 top value=100nF
C701 "CC0603MRX7R9BB103" B_Cap_0603_KEM 81.8,50.25 r270 top value=10nF
C702 "CL21B105KBFNNNG" B_Cap_0805_KEM 47.131,76.708 r270 top value=1µF
C703 "CL21B105KBFNNNG" B_Cap_0805_KEM 49.23,76.708 r270 top value=1µF
C704 "CC0805KRX7R9BB104" B_Cap_0805_KEM 51.33,76.708 r90 top value=100nF
C705 "GRM21BR71C475KE51L" B_Cap_0805_KEM 49.8,65.7 r270 top value=4.7µF
C706 "GRM21BR71C475KE51L" B_Cap_0805_KEM 47.85,65.7 r270 top value=4.7µF
D100 "SS210" "DO-214AA, SMB" 140.05,73.9 r90 top
D101 "SK54L-TP" "DO-214AB, SMC" 102.9,73.35 r180 top
D102 "SK54L-TP" "DO-214AB, SMC" 116.8,73.35 r0 top
D103 "SK54L-TP" "DO-214AB, SMC" 73.125,68.296 r180 top
D104 "SS210" "DO-214AA, SMB" 140.05,66.15 r270 top
D105 "1N4148WT" "SC-79, SOD-523" 135.7,49.6 r270 top
D106 "SK54L-TP" "DO-214AB, SMC" 73.125,75.496 r180 top
D107 "1N4148WT" "SC-79, SOD-523" 163.8,54.1 r0 top
D200 "BAT54C-7-F" "TO-236-3, SC-59, SOT-23-3" 76.35,46.536 r270 top
D300 "SS210" "DO-214AA, SMB" 136.4,59.45 r0 top
D400 "SS210" "DO-214AA, SMB" 12.96,73.87 r90 top
D500 "USBLC6-4SC6" SOT-23-6 156.931,17.8 r90 top
D501 "SS210" "DO-214AA, SMB" 121.519,10.769 r90 top
D700 "150060SS55040" LED_0603 3.541,25.008 r180 top
D701 "150060VS55040" LED_0603 3.541,23.508 r180 top
D702 "150060SS55040" LED_0603 3.541,20.507 r180 top
D703 "150060VS55040" LED_0603 3.541,22.006 r180 top
D704 "SS210" "DO-214AA, SMB" 49.95,72.5 r180 top
FB200 "FBMH1608HM601-T" FBMH1608HM601-T-Footprint-1 60,38.3 r180 top
FB201 "FBMH1608HM601-T" FBMH1608HM601-T-Footprint-1 62.5,39.3 r90 top
FB500 "FBMH1608HM601-T" FBMH1608HM601-T-Footprint-1 114.555,14.691 r180 top
FD1 "Fiducial" Fidutial+ 150,60 r0 top
FD2 "Fiducial" Fidutial+ 45,55 r0 top
FD3 "Fiducial" Fidutial+ 45,15 r0 top
FD4 "Fiducial" Fidutial+ 150,20 r0 top
GS1 "PCB FILE NAME" "PCB FILE NAME" 202.5,78.2 r0 top
H5 "9774090151R" 9774090151R 145,60 r0 top
H6 "9774090151R" 9774090151R 145,20 r0 top
H7 "9774090151R" 9774090151R 45,20 r0 top
H8 "9774090151R" 9774090151R 45,60 r0 top
J100 "43045-0400" 43045-0400-Footprint-1 176.345,71 r90 top
J101 "43650-0415" 0436500415 169.8,60.05 r180 top
J200 "NetTie" NetTie_2way_LP 65.85,34.7 r90 top net-tie
J201 "0475890001" PCBComponent#1 78.6,2.4 r180 top
J400 "2337019-1" TE_2337019-1 9.919,52.637 r90 top
J500 "J1B1211CCD" J1B1211CCD-Footprint-1 172.15,24.2 r90 top
J600 "2337019-1" TE_2337019-1 4,4 r180 top
J601 "0786463001" 0786463001-Footprint-1 8.4,35.9 r180 top
J700 "20021121-00010C4LF" 20021121-00010C4LF-Footprint-2 88.142,44.779 r270 top
L300 "VLS6045EX-3R3N" VLS6045EX 99.685,43.162 r270 top value=3.3µH
L400 "CDRH6D28NP-220NC" CDRH6D28NP 6.8,69.2 r180 top value=22µH
L401 "LQM2HPN3R3MGCL" FP-LQM2HPN_G0-IPC_B 32.744,50.837 r0 top value=3.3µH
L500 "CDRH6D28NP-220NC" CDRH6D28NP 115.342,5.969 r180 top value=22µH
L600 "SRN6045-6R8Y" SRN6045 35.244,69.876 r180 top value=6.8µH
L700 "CDRH6D28NP-220NC" CDRH6D28NP 54.6,66.4 r270 top value=22µH
Q100 "DMP4025LK3-13" "Copy of TO-252-3, DPak (2 Leads + Tab), SC-63" 155.822,55.4 r90 top
Q101 "BC857BWT1G" SC70(SOT323)-3-2.1x1.24 138.1,52.3 r180 top
Q102 "BC847BW-7-F" SC70(SOT323)-3-2.1x1.24 148.8,50.6 r0 top
Q103 "BC847BW-7-F" SC70(SOT323)-3-2.1x1.24 144.1,49.6 r90 top
Q600 "BC847BW-7-F" SC70(SOT323)-3-2.1x1.24 42.126,4.6 r270 top
Q601 "BC847BW-7-F" SC70(SOT323)-3-2.1x1.24 45.176,4.574 r270 top
R100 "RC0603FR-0736KL" Res_0603_YAG 161.7,56.1 r90 top value=36k
R102 "RC0603FR-071KL" Res_0603_YAG 135.7,46.974 r270 top value=1k
R106 "RC0603FR-0736KL" Res_0603_YAG 140.407,52.312 r90 top value=36k
R107 "RC0603FR-071KL" Res_0603_YAG 161.7,53.4 r90 top value=1k
R108 "RC0603FR-070RL" Res_0603_YAG 145,64.53 r270 top value=0
R109 "RC0603FR-070RL" Res_0603_YAG 148.85,17.35 r180 top value=0
R110 "RC0603FR-070RL" Res_0603_YAG 45,24.6 r270 top value=0
R111 "RC0603FR-070RL" Res_0603_YAG 44.5,64.7 r270 top value=0
R112 "RC0603FR-071KL" Res_0603_YAG 163.8,55.5 r180 top value=1k
R113 "RC0603FR-0736KL" Res_0603_YAG 146.3,52.2 r90 top value=36k
R116 "RC0603FR-0710KL" Res_0603_YAG 138.1,48.5 r0 top value=10k
R117 "RC0603FR-0736KL" Res_0603_YAG 135.7,52.3 r90 top value=36k
R118 "RC0603FR-07680KL" Res_0603_YAG 138.1,50.026 r180 top value=680k
R119 "RC0603FR-0736KL" Res_0603_YAG 141.959,46.575 r270 top value=36k
R120 "RC0603FR-0710KL" Res_0603_YAG 146.3,49.301 r90 top value=10k
R121 "RC0603FR-07249RL" Res_0603_YAG 83.825,51.082 r0 top value=249
R123 "RC0603FR-0736KL" Res_0603_YAG 141.96,49.301 r90 top value=36k
R200 "RC0603FR-0710KL" Res_0603_YAG 85.9,28.6 r180 top value=10k
R201 "RC0603FR-071K5L" Res_0603_YAG 79.6,8.15 r90 top value=1.5k
R202 "RC0603FR-0736KL" Res_0603_YAG 71.2,6.6 r0 top value=36k
R203 "RC0603FR-071K5L" Res_0603_YAG 80.95,8.15 r90 top value=1.5k
R204 "RC0603FR-0768KL" Res_0603_YAG 69.05,5.9 r90 top value=68k
R205 "RMCF0603FT100K" Res_0603_YAG 82.25,8.15 r90 top value=100k
R206 "RC0603FR-0768KL" Res_0603_YAG 54.7,26.95 r90 top value=68k
R207 "RC0603FR-0768KL" Res_0603_YAG 54.7,23.9 r270 top value=68k
R208 "RC0603FR-0710KL" Res_0603_YAG 52.55,27.692 r0 top value=10k
R209 "RC0603FR-0710KL" Res_0603_YAG 52.4,23.1 r0 top value=10k
R300 "RC0402FR-074K99P" Res_0402_YAG#1 117.6,23.7 r180 top value=4.99k
R301 "RC0402FR-074K99P" Res_0402_YAG#1 115.8,23.7 r0 top value=4.99k
R400 "RMCF0603FT100K" Res_0603_YAG 18.043,70.11 r90 top value=100k
R401 "RC0603FR-0736KL" Res_0603_YAG 18.1,67.5 r270 top value=36k
R402 "RC0603FR-070RL" Res_0603_YAG 19.319,58.887 r180 top value=0
R403 "RC0603FR-0710KL" Res_0603_YAG 19.6,67.5 r90 top value=10k
R404 "RC0603FR-070RL" Res_0603_YAG 22.044,59.412 r90 top value=0
R405 "RC0603FR-070RL" Res_0603_YAG 31.046,59.439 r90 top value=0
R406 "RC0603FR-070RL" Res_0603_YAG 36.969,52.637 r270 top value=0
R407 "RC0603FR-070RL" Res_0603_YAG 21.294,62.137 r90 top value=0
R408 "RC0603FR-070RL" Res_0603_YAG 23.544,59.412 r90 top value=0
R409 "RC0603FR-070RL" Res_0603_YAG 25.044,59.412 r90 top value=0
R410 "RC0603FR-070RL" Res_0603_YAG 26.544,59.412 r90 top value=0
R411 "RC0603FR-070RL" Res_0603_YAG 28.044,59.412 r90 top value=0
R412 "RC0603FR-070RL" Res_0603_YAG 22.794,62.137 r90 top value=0
R413 "RC0603FR-070RL" Res_0603_YAG 24.294,62.137 r90 top value=0
R414 "RC0603FR-070RL" Res_0603_YAG 25.794,62.137 r90 top value=0
R415 "RC0603FR-070RL" Res_0603_YAG 27.294,62.137 r90 top value=0
R416 "RC0603FR-070RL" Res_0603_YAG 29.544,59.437 r90 top value=0
R500 "RC0603FR-071K5L" Res_0603_YAG 137.378,5.122 r0 top value=1.5k
R501 "RC0603FR-0710KL" Res_0603_YAG 134.218,5.997 r270 top value=10k
R502 "RC0603FR-0710KL" Res_0603_YAG 134.243,8.548 r270 top value=10k
R503 "RC0603FR-0710KL" Res_0603_YAG 134.243,11.072 r90 top value=10k
R504 "RC0603FR-0749R9L" Res_0603_YAG 152.178,8.922 r90 top value=49.9
R505 "RC0603FR-0749R9L" Res_0603_YAG 152.178,11.472 r270 top value=49.9
R506 "RC0603FR-0749R9L" Res_0603_YAG 153.478,4.865 r270 top value=49.9
R507 "RC0603FR-0749R9L" Res_0603_YAG 153.478,7.415 r90 top value=49.9
R508 "RC0603FR-0733RL" Res_0603_YAG 132.278,9.222 r0 top value=33
R509 "RC0603FR-0733RL" Res_0603_YAG 132.278,10.522 r0 top value=33
R510 "RC0603FR-0710KL" Res_0603_YAG 142.13,3.29 r180 top value=10k
R511 "RC0603FR-0733RL" Res_0603_YAG 132.253,6.622 r0 top value=33
R512 "RC0603FR-0733RL" Res_0603_YAG 140.67,1.96 r180 top value=33
R513 "RC0603FR-0712K1L" Res_0603_YAG 146.903,9.822 r180 top value=12.1k
R514 "RC0603FR-0710KL" Res_0603_YAG 137.478,7.348 r0 top value=10k
R515 "RC0603FR-070RL" Res_0603_YAG 168.217,13.611 r0 top value=0
R516 "RMCF0603FT100K" Res_0603_YAG 126.667,6.944 r90 top value=100k
R517 "RMCF0603FT31K6" Res_0603_YAG 126.7,3.5 r0 top value=31.6k
R518 "RC0603FR-07249RL" Res_0603_YAG 162.7,13.611 r0 top value=249
R519 "RC0603FR-07249RL" Res_0603_YAG 162.7,33.3 r0 top value=249
R520 "RC0603FR-0710KL" Res_0603_YAG 126.7,5 r180 top value=10k
R521 "RC0603FR-0710KL" Res_0603_YAG 162.7,15.15 r180 top value=10k
R600 "RC0402JR-070RL" Res_0402_YAG#1 17.65,1.8 r180 top value=0
R601 "RC0402JR-070RL" Res_0402_YAG#2 7.3,9.3 r180 top value=0
R602 "RC0603FR-0749R9L" Res_0603_YAG 12.5,27.1 r0 top value=49.9
R603 "RC0603FR-0710KL" Res_0603_YAG 27.05,1.8 r180 top value=10k
R604 "RC0603FR-0710KL" Res_0603_YAG 39.826,5.125 r90 top value=10k
R605 "RC0603FR-0710KL" Res_0603_YAG 47.526,5.125 r90 top value=10k
R606 "RC0603FR-0710KL" Res_0603_YAG 30.96,31.545 r90 top value=10k
R607 "RC0603FR-0710KL" Res_0603_YAG 42.126,8.6 r0 top value=10k
R608 "RC0603FR-0710KL" Res_0603_YAG 42.126,6.975 r0 top value=10k
R609 "RC0603FR-0710KL" Res_0603_YAG 45.176,8.6 r0 top value=10k
R610 "RC0603FR-0710KL" Res_0603_YAG 45.176,7 r0 top value=10k
R611 "RC0603FR-0710KL" Res_0603_YAG 21.094,36.08 r180 top value=10k
R612 "RC0603FR-0710KL" Res_0603_YAG 21.7,27.05 r0 top value=10k
R613 "RC0603FR-0736KL" Res_0603_YAG 42.719,69.836 r0 top value=36k
R614 "RC0603FR-070RL" Res_0603_YAG 42.719,76.276 r90 top value=0
R615 "RC0603FR-0736KL" Res_0603_YAG 41.338,76.276 r270 top value=36k
R616 "RC0603FR-0710KL" Res_0603_YAG 42.719,71.476 r180 top value=10k
R700 "RC0603FR-07330RL" Res_0603_YAG 92.551,14.25 r90 top value=330
R701 "RC0603FR-07330RL" Res_0603_YAG 91.051,14.25 r90 top value=330
R702 "RC0603FR-07330RL" Res_0603_YAG 88.05,14.25 r90 top value=330
R703 "RC0603FR-07330RL" Res_0603_YAG 89.55,14.25 r90 top value=330
R704 "RC0603FR-0710KL" Res_0603_YAG 53.49,3.562 r180 top value=10k
R705 "RC0603FR-0710KL" Res_0603_YAG 53.49,4.837 r180 top value=10k
R706 "RC0603FR-0710KL" Res_0603_YAG 53.49,6.087 r180 top value=10k
R707 "RC0603FR-0710KL" Res_0603_YAG 53.49,7.458 r180 top value=10k
R708 "RC0603FR-07330RL" Res_0603_YAG 92.551,7.125 r270 top value=330
R709 "RC0603FR-07330RL" Res_0603_YAG 91.051,7.125 r270 top value=330
R710 "RC0603FR-07330RL" Res_0603_YAG 88.05,7.125 r270 top value=330
R711 "RC0603FR-07330RL" Res_0603_YAG 92.551,11.5 r90 top value=330
R712 "RC0603FR-07330RL" Res_0603_YAG 91.051,11.5 r90 top value=330
R713 "RC0603FR-07330RL" Res_0603_YAG 88.05,11.5 r90 top value=330
R714 "RC0603FR-07330RL" Res_0603_YAG 89.55,11.5 r90 top value=330
R715 "RC0603FR-07330RL" Res_0603_YAG 89.548,7.125 r270 top value=330
R716 "RC0603FR-0710KL" Res_0603_YAG 79.79,49.45 r180 top value=10k
R717 "RC0603FR-0710KL" Res_0603_YAG 80.85,37.525 r90 top value=10k
R718 "RMCF0603FT100K" Res_0603_YAG 53.69,77.643 r180 top value=100k
R719 "RMCF0603FT31K6" Res_0603_YAG 57.833,77.023 r0 top value=31.6k
R720 "RC0603FR-0710KL" Res_0603_YAG 81.561,35.311 r0 top value=10k
R721 "RC0603FR-0710KL" Res_0603_YAG 82.417,37.529 r270 top value=10k
R722 "RC0603FR-0710KL" Res_0603_YAG 57.833,78.523 r180 top value=10k
S100 "CSS-1210TB" PCBComponent#2 3,58.7 r270 top
S700 "218-4LPSTJ" 218-4LPSTJ 58.99,5.462 r270 top
SW100 "430181038816" 430181038816 4.1,58.7 r90 top
TP100 "0.75 mm" 0.75mm 137.375,69.054 r90 top
TP101 "0.75 mm" 0.75mm 102.15,50.7 r90 top
TP102 "0.75 mm" 0.75mm 145.1,54.1 r180 top
TP200 "0.75 mm" 0.75mm 89.65,29.35 r180 top
TP201 "0.75 mm" 0.75mm 89.65,31.05 r180 top
TP202 "0.75 mm" 0.75mm 80.5,47.9 r0 top
TP203 "0.75 mm" 0.75mm 46.174,64.8 r180 top
TP204 "0.75 mm" 0.75mm 65.85,5.964 r90 top
TP400 "0.75 mm" 0.75mm 5.2,77.626 r180 top
TP600 "0.75 mm" 0.75mm 37.7,8.2 r270 top
TP601 "0.75 mm" 0.75mm 37.7,4.9 r270 top
TP602 "0.75 mm" 0.75mm 37.7,7.1 r270 top
TP603 "0.75 mm" 0.75mm 24,26.8 r270 top
TP604 "0.75 mm" 0.75mm 37.7,18.4 r270 top
TP605 "0.75 mm" 0.75mm 37.7,17.3 r270 top
TP606 "0.75 mm" 0.75mm 23.15,2.4 r270 top
TP607 "0.75 mm" 0.75mm 22.05,2.4 r270 top
TP608 "0.75 mm" 0.75mm 37.7,12.773 r180 top
TP609 "0.75 mm" 0.75mm 37.7,11.673 r180 top
TP610 "0.75 mm" 0.75mm 37.7,22.85 r270 top
TP611 "0.75 mm" 0.75mm 37.7,21.696 r270 top
TP612 "0.75 mm" 0.75mm 29.969,70.11 r90 top
TP700 "0.75 mm" 0.75mm 50.9,61.1 r90 top
TP701 "0.75 mm" 0.75mm 84.535,35.311 r0 top
U301 "NJM7812SDL1-TE1" "TO-252-3, DPak (2 Leads + Tab), SC-63" 128.765,59.781 r0 top
U400 "LV2862XLVDDCR" SOT-23-6 14.8,68.1 r90 top
U401 "LFD182G45DCJD247" CAF-50P160X80-6N 18.694,52.637 r180 top
U402 "nRF7002-QFAAB0" QFN48N 25.294,53.237 r0 top value=nRF7002-QFAA
U500 "LAN8742A-CZ-TR" 24-VFQFN 142.678,8.173 r270 top
U501 "LV2862XLVDDCR" SOT-23-6 123.359,5 r90 top
U601 "TXB0108DQSR" TXB0108DQSR-Footprint-1 27.76,32.27 r90 top
U602 "ECLAMP2465T.TCT" ECLAMP2465T.TCT-Footprint-1 19.375,33.657 r270 top
U603 "TPS563300DRLR" SOT-583 40.094,73.476 r270 top
U700 "LV2862XLVDDCR" SOT-23-6 55.7,74.4 r180 top
U701 "STWD100YNYWY3F" "SOT23-5 ST" 85.449,38.225 r0 top
Y200 "CM13032768DZFT" CM130 77.1,39.3 r90 top value=1.25E-11F
Y201 "ABM10-25.000MHZ-E20-T" "4-SMD, No Lead" 69.85,37.29 r90 top
Y400 "830069527" 1612_crystal 26.619,47.512 r180 top
Y500 "ABM10-25.000MHZ-E20-T" "4-SMD, No Lead" 142.378,14.073 r270 top

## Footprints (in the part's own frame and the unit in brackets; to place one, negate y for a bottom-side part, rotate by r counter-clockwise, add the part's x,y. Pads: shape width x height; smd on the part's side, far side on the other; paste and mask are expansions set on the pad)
0.75mm [mm]
  round 0.75 smd paste-2539.97 mask+0: 1(0,0)
"4-SMD, No Lead" [mm]
  rrect10% 1.15x1 smd paste-0.05 mask+0.05: 1(-0.875,-0.65) 2(0.875,-0.65) 3(0.875,0.65) 4(-0.875,0.65)
  silkscreen extent -1.68,-1.38 -1.2,-0.9, body extent -1.24,-1 1.24,1, height 0.56
24-VFQFN [mm] "24-VFQFN Exposed Pad"
  rrect50% 0.7x0.3 smd paste-0.05 mask+0.05: 1(-1.9,1.25) 2(-1.9,0.75) 3(-1.9,0.25) 4(-1.9,-0.25) 5(-1.9,-0.75) 6(-1.9,-1.25) 13(1.9,-1.25) 14(1.9,-0.75) 15(1.9,-0.25) 16(1.9,0.25) 17(1.9,0.75) 18(1.9,1.25)
  rrect50% 0.3x0.7 smd paste-0.05 mask+0.05: 7(-1.25,-1.9) 8(-0.75,-1.9) 9(-0.25,-1.9) 10(0.25,-1.9) 11(0.75,-1.9) 12(1.25,-1.9) 19(1.25,1.9) 20(0.75,1.9) 21(0.25,1.9) 22(-0.25,1.9) 23(-0.75,1.9) 24(-1.25,1.9)
  rect 2.49x2.49 smd paste-5 mask+0.05: 25(0,0)
  silkscreen extent -2.67,-2.12 2.12,2.12, body extent -2,-2 2.01,2.01, height 0.9
218-4LPSTJ [mm]
  rrect50% 0.76x2 smd paste-0.05 mask+0.05: 1(-1.91,-2.5) 2(-0.64,-2.5) 3(0.63,-2.5) 4(1.9,-2.5) 5(1.9,2.5) 6(0.63,2.5) 7(-0.64,2.5) 8(-1.91,2.5)
  silkscreen extent -3.4,-3.61 3.4,2.9, body extent -3.3,-2.8 3.3,2.8, height 2.42
1612_crystal [mm]
  rect 0.65x0.55 smd paste+0 mask+0.1: 1(-0.575,-0.425) 2(0.575,-0.425) 3(0.575,0.425) 4(-0.575,0.425)
  silkscreen extent -1.24,-0.9 1.1,0.9, body extent -0.8,-0.6 0.8,0.6, height 0.4
43045-0400-Footprint-1 [mm] "(DON'T CHANGE) Template component PCB"
  rect 1.57x1.57 hole 1.02 paste-2539.97 mask+0: 1(1.5,3.965)
  round 1.57 hole 1.02 paste-2539.97 mask+0: 2(-1.5,3.965) 3(1.5,6.965) 4(-1.5,6.965)
  round 3 hole 3 unplated paste-2539.97 mask+0: ""(0,-0.355)
  silkscreen extent -5.2,-2.81 5.97,5.08, body extent -5.3,-5.31 5.3,7.85, height 0.25
20021121-00010C4LF-Footprint-2 [mm] "(DON'T CHANGE) Template component PCB"
  round 0.863 smd mask+0.05: 1(2.485,0.52) 2(2.485,-0.75) 3(1.215,0.52) 4(1.215,-0.75) 5(-0.055,0.52) 6(-0.055,-0.75) 7(-1.325,0.52) 8(-1.325,-0.75) 9(-2.595,0.52) 10(-2.595,-0.75)
  rrect50% 0.76x2.05 smd mask+0.05: 1(2.49,1.675) 2(2.49,-1.875) 3(1.22,1.675) 4(1.22,-1.875) 5(-0.05,1.675) 6(-0.05,-1.875) 7(-1.32,1.678) 8(-1.32,-1.878) 9(-2.59,1.678) 10(-2.59,-1.878)
  round 0.524 hole 1.1 unplated: TH1(3.755,-0.115) TH2(-3.865,-1.131) TH3(-3.865,0.901)
  Top Layer pour cut-out: 2.475,-0.765 2.475,0.535 -2.595,0.535 -2.595,-0.765
  silkscreen extent -5.13,-3.35 3.22,3.15, body extent -3.2,-2.85 3.15,2.65, height 4.5
0436500415 [mm]
  rect 1.605x1.605 hole 1.07 mask+0.1: 1(4.5,0)
  round 1.605 hole 1.07 mask+0.1: 2(1.5,0) 3(-1.5,0) 4(-4.5,0)
  round 1.32 hole 1.32 unplated mask+0.1: h1(-7.5,-1.96) h2(7.5,-1.96)
  silkscreen extent -7.83,-2.47 8.47,1.9, body extent -7.83,-2.47 7.83,3.1, height 10
0786463001-Footprint-1 [mm] "(DON'T CHANGE) Template component PCB"
  rrect50% 1.15x0.65 smd mask+0.05: C1(-6.865,2.755) C2(-6.865,0.215) C3(-6.865,-2.325) C5(-6.865,4.025) C6(-6.865,1.485) C7(-6.865,-1.055)
  rrect50% 1.7x1.4 smd mask+0.05: MH1(6.865,6.105) MH6(6.865,-6.105)
  rrect50% 1.3x0.45 smd mask+0.05: MH2(-2.695,6.27) MH3(-4.695,6.27) MH4(-4.695,-6.27) MH5(-2.695,-6.27)
  rrect50% 0.8x0.54 smd mask+0.05: X1(6.285,2.54) X2(6.285,-2.54)
  Top Layer keep-out region: -5.1,-5.875 5.725,-5.875 5.725,5.875 -5.1,5.875
  silkscreen extent -7.68,-6.73 7.68,6.73, body extent -7.28,-6.52 8.17,6.53, height 1.45
9774090151R [mm] "(DON'T CHANGE) Template component PCB"
  round 6 hole 3.7 paste-2539.97 mask+0.05: 1(0,0)
  silkscreen extent -3.22,-3.22 3.22,3.22, body extent -2.55,-2.55 2.55,2.55, height 9
430181038816 [mm]
  rect 2x1.4 smd: 1(-3.5,1.5) 2(3.5,1.5) 3(-3.5,-1.5) 4(3.5,-1.5)
  silkscreen extent -4.8,-2.5 4.8,2.5, body extent -3.75,-2.27 3.75,2.23, height 3.8
B_Cap_0402_KEM [mm] "0402 Capasitor footprint B Density based on KEMET Commercial Grade Ceramic Capasitiors"
  rrect30% 0.62x0.62 smd paste+0 mask+0.05: 1(-0.45,0) 2(0.45,0)
  Top Layer pour cut-out: -0.14,0.222 0.14,0.222 0.14,-0.222 -0.14,-0.222
  silkscreen extent -0.99,-0.54 0.99,0.54, body extent -0.53,-0.27 0.53,0.28, height 0.55
B_Cap_0603_KEM [mm] "0603 Capasitor footprint B Density based on KEMET Commercial Grade Ceramic Capasitiors"
  rrect30% 0.95x1 smd paste+0 mask+0.05: 1(-0.8,0) 2(0.8,0)
  silkscreen extent -1.5,-0.72 1.5,0.72, body extent -0.87,-0.48 0.87,0.48, height 0.87
B_Cap_0805_KEM [mm] "0805 Capasitor footprint B Density based on KEMET Commercial Grade Ceramic Capasitiors"
  rrect30% 1.15x1.45 smd paste-0.05 mask+0.05: 1(-0.9,0) 2(0.9,0)
  silkscreen extent -1.7,-0.95 1.7,0.95, body extent -1.1,-0.72 1.1,0.72, height 0.88
B_Cap_1206_KEM [mm] "1206 Capasitor footprint B Density based on KEMET Commercial Grade Ceramic Capasitiors"
  rrect30% 1.15x1.8 smd paste-0.05 mask+0.05: 1(-1.5,0) 2(1.5,0)
  silkscreen extent -2.3,-1.12 2.3,1.12, body extent -1.7,-0.9 1.7,0.9, height 1
BH-25F-1 [mm]
  round 2 hole 1.3 mask+0.1: 1(-8,0) 2(12,0)
  silkscreen extent -11.35,-11 13.33,11, body extent -11.4,-11 13.1,11, height 8.5
CAF-50P160X80-6N [mm]
  rrect20% 0.5x0.25 smd mask+0.05: 1(-0.45,0.5) 2(-0.45,0) 3(-0.45,-0.5) 5(0.45,-0.5) 6(0.45,0) 7(0.45,0.5)
  Top Layer region: 0.786,0.375 0.2,0.375 0,0.175 0,-0.175 0.2,-0.375 0.789,-0.375 1.175,-0.761 1.175,-0.95 0.15,-0.95 0,-0.8 0,-0.375 -0.25,-0.125 -0.8,-0.125 -0.9,-0.225 -1,-0.225 -1,0.225 -0.9,0.225 -0.802,0.127 -0.248,0.127 0,0.375 0,0.8 0.15,0.95 1.175,0.95 1.175,0.764
  silkscreen extent -1.1,-1 1,1.02, body extent -0.53,-0.88 0.47,0.88, height 0.7
CDRH6D28NP [mm]
  rect 2.65x7.3 smd paste-0.05 mask+0.05: 1(-2.325,0) 2(2.325,0)
  silkscreen extent -3.88,-3.88 3.88,3.88, body extent -3.35,-3.25 3.35,3.25, height 3.1
CM130 [mm] "(DON'T CHANGE) Template component PCB"
  rrect50% 1.2x0.6 smd paste-0.05 mask+0.05: 1(-3.15,-0.45) 2(3.15,-0.45) 3(3.15,0.45) 4(-3.15,0.45)
  silkscreen extent -3.98,-1.7 3.98,0.97, body extent -3.5,-0.75 3.5,0.75, height 1.4
"Copy of TO-252-3, DPak (2 Leads + Tab), SC-63" [mil]
  rrect10% 55x90 smd: 1(-90,-131.69) 2(90,-131.69)
  rrect10% 224.02x243.31 smd: 3(0,121.65)
  silkscreen extent -129,-62 129,-7, body extent -129,-158 129,233, height 96
"DO-214AA, SMB" [mm] "DO-214AA, SMB"
  rrect30% 2.5x2.3 smd paste-0.05 mask+0.05: 1(-2.15,0) 2(2.15,0)
  silkscreen extent -2.39,-2.03 1.85,2.03, body extent -2.75,-1.95 2.75,1.95, height 2.45
"DO-214AB, SMC" [mm] "DO-214AB, SMC"
  rrect30% 2.5x3.3 smd paste-0.05 mask+0.05: 1(-3.45,0) 2(3.45,0)
  silkscreen extent -3.65,-3.3 3.39,3.3, body extent -4.07,-3.05 4.07,3.05, height 2.4
ECLAMP2465T.TCT-Footprint-1 [mm] "(DON'T CHANGE) Template component PCB"
  rrect50% 0.58x0.2 smd paste+0 mask+0.05: 1(-0.635,0.6) 2(-0.635,0.2) 3(-0.635,-0.2) 4(-0.635,-0.6) 5(0.635,-0.6) 6(0.635,-0.2) 7(0.635,0.2) 8(0.635,0.6)
  rect 0.3x1.4 smd paste-2 mask+0.05: 9(0,0)
  silkscreen extent -1.25,-1.04 0.65,1.04, body extent -0.69,-0.89 0.69,0.89, height 0.43
EMVA500ARA471MKG5S [mm]
  rect 5.7x2.5 smd paste+0 mask+0.1: 1(-4.85,0) 2(4.85,0)
  silkscreen extent -7.82,-6.85 7.2,6.85, body extent -6.85,-6.5 6.85,6.5, height 16.05
FBMH1608HM601-T-Footprint-1 [mm] "(DON'T CHANGE) Template component PCB"
  rrect25% 1x1 smd paste-0.05 mask+0.05: 1(-1,0) 2(1,0)
  silkscreen extent -1.73,-0.72 1.73,0.72, body extent -0.8,-0.4 0.8,0.4, height 0.9
Fidutial+ [mm]
  round 1 smd paste-2539.97 mask+0.75: Fiducial(0,0)
  Top Layer keep-out circle w0.01: c0,0 r1.25
FP-LQM2HPN_G0-IPC_B [mm]
  rect 1.355x2.206 smd paste-0.05 mask+0.05: 1(-1.026,0) 2(1.026,0)
  silkscreen extent -1.7,-1.33 1.7,1.33, body extent -1.25,-1 1.25,1, height 1
J1B1211CCD-Footprint-1 [mm] "(DON'T CHANGE) Template component PCB"
  rect 1.4x1.4 hole 0.9 paste-2539.97 mask+0: 1(-4.445,6.45)
  round 1.4 hole 0.9 paste-2539.97 mask+0: 2(-3.175,8.99) 3(-1.905,6.45) 4(-0.635,8.99) 5(0.635,6.45) 6(1.905,8.99) 7(3.175,6.45) 8(4.445,8.99)
  round 1.57 hole 1.02 paste-2539.97 mask+0: 9(-6.325,-4.98) 10(-3.785,-3.28) 11(3.785,-4.98) 12(6.325,-3.28)
  round 2.45 hole 1.6 paste-2539.97 mask+0: 13(-7.875,3.15) 14(7.875,3.15)
  round 3.25 hole 3.25 unplated paste-2539.97 mask+0: 15(-5.715,0.1) 16(5.715,0.1)
  silkscreen extent -9.75,-7.1 8.13,10.78, body extent -9.2,-10.87 9.2,10.87, height 0.25
LED_0603 [mm]
  rrect50% 0.8x0.8 smd paste+0 mask+0.05: 1(-0.825,0) 2(0.825,0)
  silkscreen extent -1.45,-0.63 -0.5,0.63, body extent -0.82,-0.38 0.83,0.35, height 0.68
NetTie_2way_LP [mil]
  rrect5% 20x12 smd paste-100: 1(-14,0) 2(14,0)
"PCB FILE NAME" [mm]
PCBComponent#1 [mm]
  rect 0.4x1.35 smd paste+0 mask+0.05: 1(1.3,-2.675) 2(0.65,-2.675) 3(0,-2.675) 4(-0.65,-2.675) 5(-1.3,-2.675)
  rect 1.175x1.9 smd paste+0 mask+0.1: 6(3.187,0) 9(-3.187,0)
  rrect50% 1.175x1.9 smd paste+0 mask+0.1: 6(3.725,0) 9(-3.725,0)
  rrect50% 1.175x1.9 hole 1.3 slot 0.6 at 0 deg mask+0.1: 6(4.175,0) 9(-4.175,0)
  rect 1.8x1.9 smd paste+0 mask+0.1: 7(1.15,0) 8(-1.15,0)
  oval 0.9x1.5 hole 0.85 slot 0.65 at 0 deg mask+0.05: 10(2.225,-3) 11(-2.225,-3)
  silkscreen extent -4.99,-4.7 4.99,1.28, body extent -4.35,-3.19 4.3,2.7, height 2.74
PCBComponent#2 [mm]
  round 0.1 hole 0.805: 0(-3.15,-1.875) 0(3.15,-1.875)
  rrect50% 1x2.5 smd: 1(-3,1.875) 2(-1,1.875) 3(1,1.875)
  silkscreen extent -4.57,-2.1 4.58,-1.4, body extent -4.42,-3.97 4.42,2.53, height 2
QFN48N [mm]
  oval 0.7x0.2 smd paste+0 mask+0.05: 1(-3,2.2) 2(-3,1.8) 3(-3,1.4) 4(-3,1) 5(-3,0.6) 6(-3,0.2) 7(-3,-0.2) 8(-3,-0.6) 9(-3,-1) 10(-3,-1.4) 11(-3,-1.8) 12(-3,-2.2) 25(3,-2.2) 26(3,-1.8) 27(3,-1.4) 28(3,-1) 29(3,-0.6) 30(3,-0.2) 31(3,0.2) 32(3,0.6) 33(3,1) 34(3,1.4) 35(3,1.8) 36(3,2.2)
  oval 0.2x0.7 smd paste+0 mask+0.05: 13(-2.2,-3) 14(-1.8,-3) 15(-1.4,-3) 16(-1,-3) 17(-0.6,-3) 18(-0.2,-3) 19(0.2,-3) 20(0.6,-3) 21(1,-3) 22(1.4,-3) 23(1.8,-3) 24(2.2,-3) 37(2.2,3) 38(1.8,3) 39(1.4,3) 40(1,3) 41(0.6,3) 42(0.2,3) 43(-0.2,3) 44(-0.6,3) 45(-1,3) 46(-1.4,3) 47(-1.8,3) 48(-2.2,3)
  rect 4.6x4.6 smd paste-5 mask+0.05: 49(0,0)
  silkscreen extent -4.02,-3.18 3.18,3.18, body extent -3.02,-3.02 3.02,3.02, height 0.86
Res_0402_YAG#1 [mm] "0402 Resistor footprint based on YAGEO General Purpose Chip Resistor RC series"
  rrect30% 0.45x0.6 smd paste+0 mask+0.05: 1(-0.425,0) 2(0.425,0)
  Top Layer pour cut-out: -0.2,0.232 0.2,0.232 0.2,-0.232 -0.2,-0.232
  silkscreen extent -0.88,-0.53 0.87,0.52, body extent -0.5,-0.25 0.5,0.25, height 0.4
Res_0402_YAG#2 [mm] "0402 Resistor footprint based on YAGEO General Purpose Chip Resistor RC series"
  rrect30% 0.47x0.62 smd paste+0 mask+0.05: 1(-0.425,0) 2(0.425,0)
  Top Layer pour cut-out: -0.2,0.232 0.2,0.232 0.2,-0.232 -0.2,-0.232
  silkscreen extent -0.88,-0.53 0.87,0.52, body extent -0.5,-0.25 0.5,0.25, height 0.4
Res_0603_YAG [mm] "0603 Resistor footprint based on YAGEO General Purpose Chip Resistor RC series"
  rrect30% 0.65x0.85 smd paste+0 mask+0.05: 1(-0.725,0) 2(0.725,0)
  silkscreen extent -1.28,-0.65 1.28,0.65, body extent -0.8,-0.4 0.8,0.4, height 0.55
SC70(SOT323)-3-2.1x1.24 [mm]
  rrect50% 0.9x0.7 smd paste+0 mask+0.05: 1(-0.95,0.65) 2(-0.95,-0.65) 3(0.95,0)
  silkscreen extent -0.7,-1.27 0.7,1.27, body extent -1.12,-1.1 1.12,1.1, height 1.1
"SC-79, SOD-523" [mm] "SC-79, SOD-523"
  rrect30% 0.6x0.7 smd paste+0 mask+0.05: 1(-0.7,0) 2(0.7,0)
  silkscreen extent -1.22,-0.58 0.64,0.58, body extent -0.82,-0.43 0.82,0.43, height 0.66
"SOT23-5 ST" [mm]
  rrect25% 1.1x0.6 smd paste+0 mask+0.05: 1(-1.3,0.95) 2(-1.3,0) 3(-1.3,-0.95) 4(1.3,-0.95) 5(1.3,0.95)
  silkscreen extent -2.32,-1.68 1.4,1.73, body extent -1.41,-1.45 1.41,1.45, height 1.45
SOT-23-6 [mm]
  rrect50% 1.1x0.6 smd paste-0.05 mask+0.05: 1(-1.3,0.95) 2(-1.3,0) 3(-1.3,-0.95) 4(1.3,-0.95) 5(1.3,0) 6(1.3,0.95)
  silkscreen extent -2.07,-1.45 0.5,1.67, body extent -1.4,-1.45 1.4,1.45, height 1.55
SOT-583 [mm] "(DON'T CHANGE) Template component PCB"
  rrect25% 0.67x0.3 smd paste+0 mask+0.05: 1(-0.74,0.75) 2(-0.74,0.25) 3(-0.74,-0.25) 4(-0.74,-0.75) 5(0.74,-0.75) 6(0.74,-0.25) 7(0.74,0.25) 8(0.74,0.75)
  silkscreen extent -1.16,-1.2 0.6,1.45, body extent -0.8,-1.05 0.8,1.05, height 0.6
SRN6045 [mm]
  rect 2x6 smd paste-0.05 mask+0.1: 1(-2.15,0) 2(2.15,0)
  silkscreen extent -3.37,-3.22 3.37,3.22, body extent -3,-3 3,3, height 4.5
TE_2337019-1 [mm]
  rect 1x1.05 smd paste-0.05 mask+0.05: 1(0,-1.525)
  rect 1.05x2.2 smd paste-0.05 mask+0.05: G1(-1.475,0) G2(1.475,0)
  Keep-Out Layer region: 0.875,-0.9 -0.875,-0.9 -0.875,1.1 0.875,1.1
  silkscreen extent -2,-2.7 2,1.52, body extent -1.5,-1.55 1.5,1.55, height 1.25
"TO-236-3, SC-59, SOT-23-3" [mm] "TO-236-3, SC-59, SOT-23-3"
  rrect30% 0.85x0.6 smd paste+0 mask+0.05: 1(-1.075,0.95) 2(-1.075,-0.95) 3(1.075,0)
  silkscreen extent -0.97,-1.73 0.9,1.73, body extent -1.25,-1.5 1.25,1.5, height 1.09
"TO-252-3, DPak (2 Leads + Tab), SC-63" [mm]
  rrect50% 1.6x3 smd paste+0 mask+0.05: 1(-2.285,-3.59) 3(2.285,-3.59)
  rect 5.8x6.2 smd paste-2539.97 mask+0.05: 4(0,3.59)
  silkscreen extent -3.53,-1.91 3.53,5.86, body extent -3.35,-4.52 3.35,5.83, height 2.41
TXB0108DQSR-Footprint-1 [mm] "(DON'T CHANGE) Template componemt PCB"
  rrect20% 1.1x0.2 smd paste-1000 mask+0.05: 1(-0.85,1.8)
  rrect20% 1x0.2 smd paste-1000 mask+0.05: 2(-0.9,1.4) 3(-0.9,1) 4(-0.9,0.6) 5(-0.9,0.2) 6(-0.9,-0.2) 7(-0.9,-0.6) 8(-0.9,-1) 9(-0.9,-1.4) 10(-0.9,-1.8) 11(0.9,-1.8) 12(0.9,-1.4) 13(0.9,-1) 14(0.9,-0.6) 15(0.9,-0.2) 16(0.9,0.2) 17(0.9,0.6) 18(0.9,1) 19(0.9,1.4) 20(0.9,1.8)
  silkscreen extent -1.78,-2.27 1.02,2.4, body extent -0.98,-2 1.02,2, height 0.55
VLS6045EX [mm]
  rect 1.9x5.1 smd paste+0 mask+0.1: 1(-2.1,0) 2(2.1,0)
  silkscreen extent -3,-3 3,3, body extent -3,-3 3,3, height 4.5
